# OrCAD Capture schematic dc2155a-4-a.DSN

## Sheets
1 PAGE2: size Custom; title: HIGH VOLTAGE DUAL STEP-DOWN DC/DC CONVERTER; rev: 4; company: TM; note: WITH POWER SYSTEM MANAGEMENT
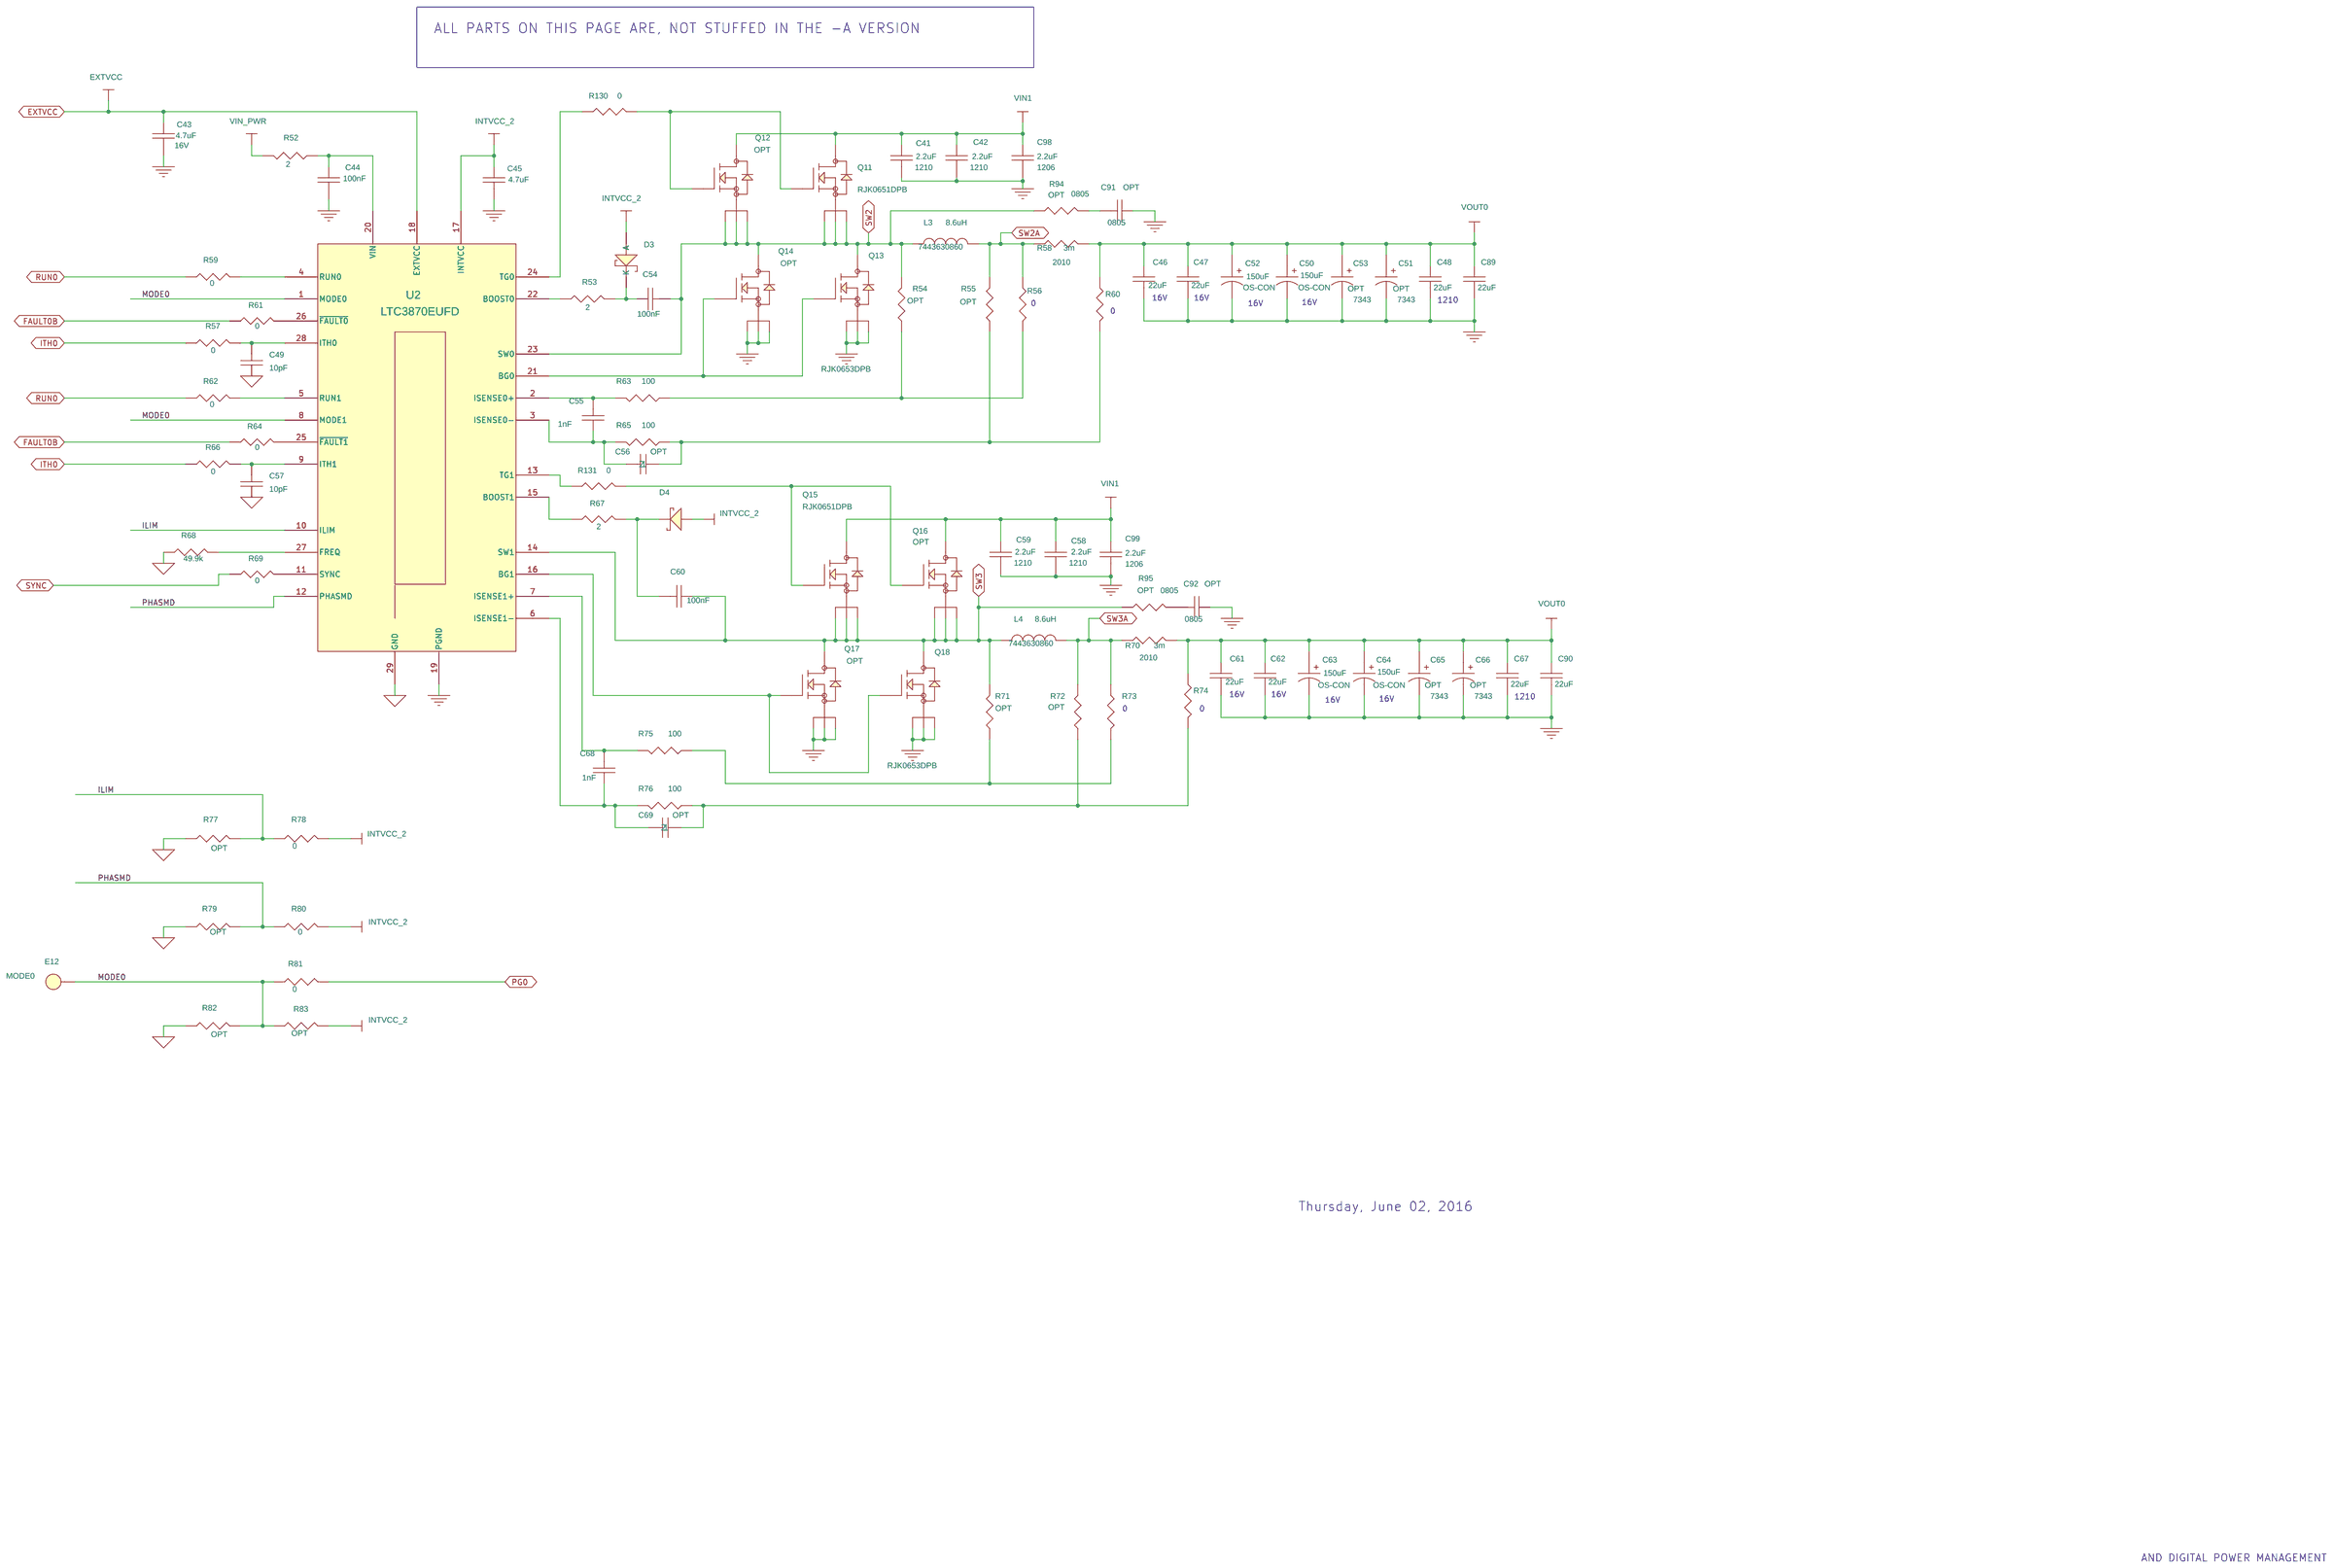
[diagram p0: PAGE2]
2 PAGE1: size Custom; note: DC/DC CONVERTER with POWER SYSTEM MANAGEMENT
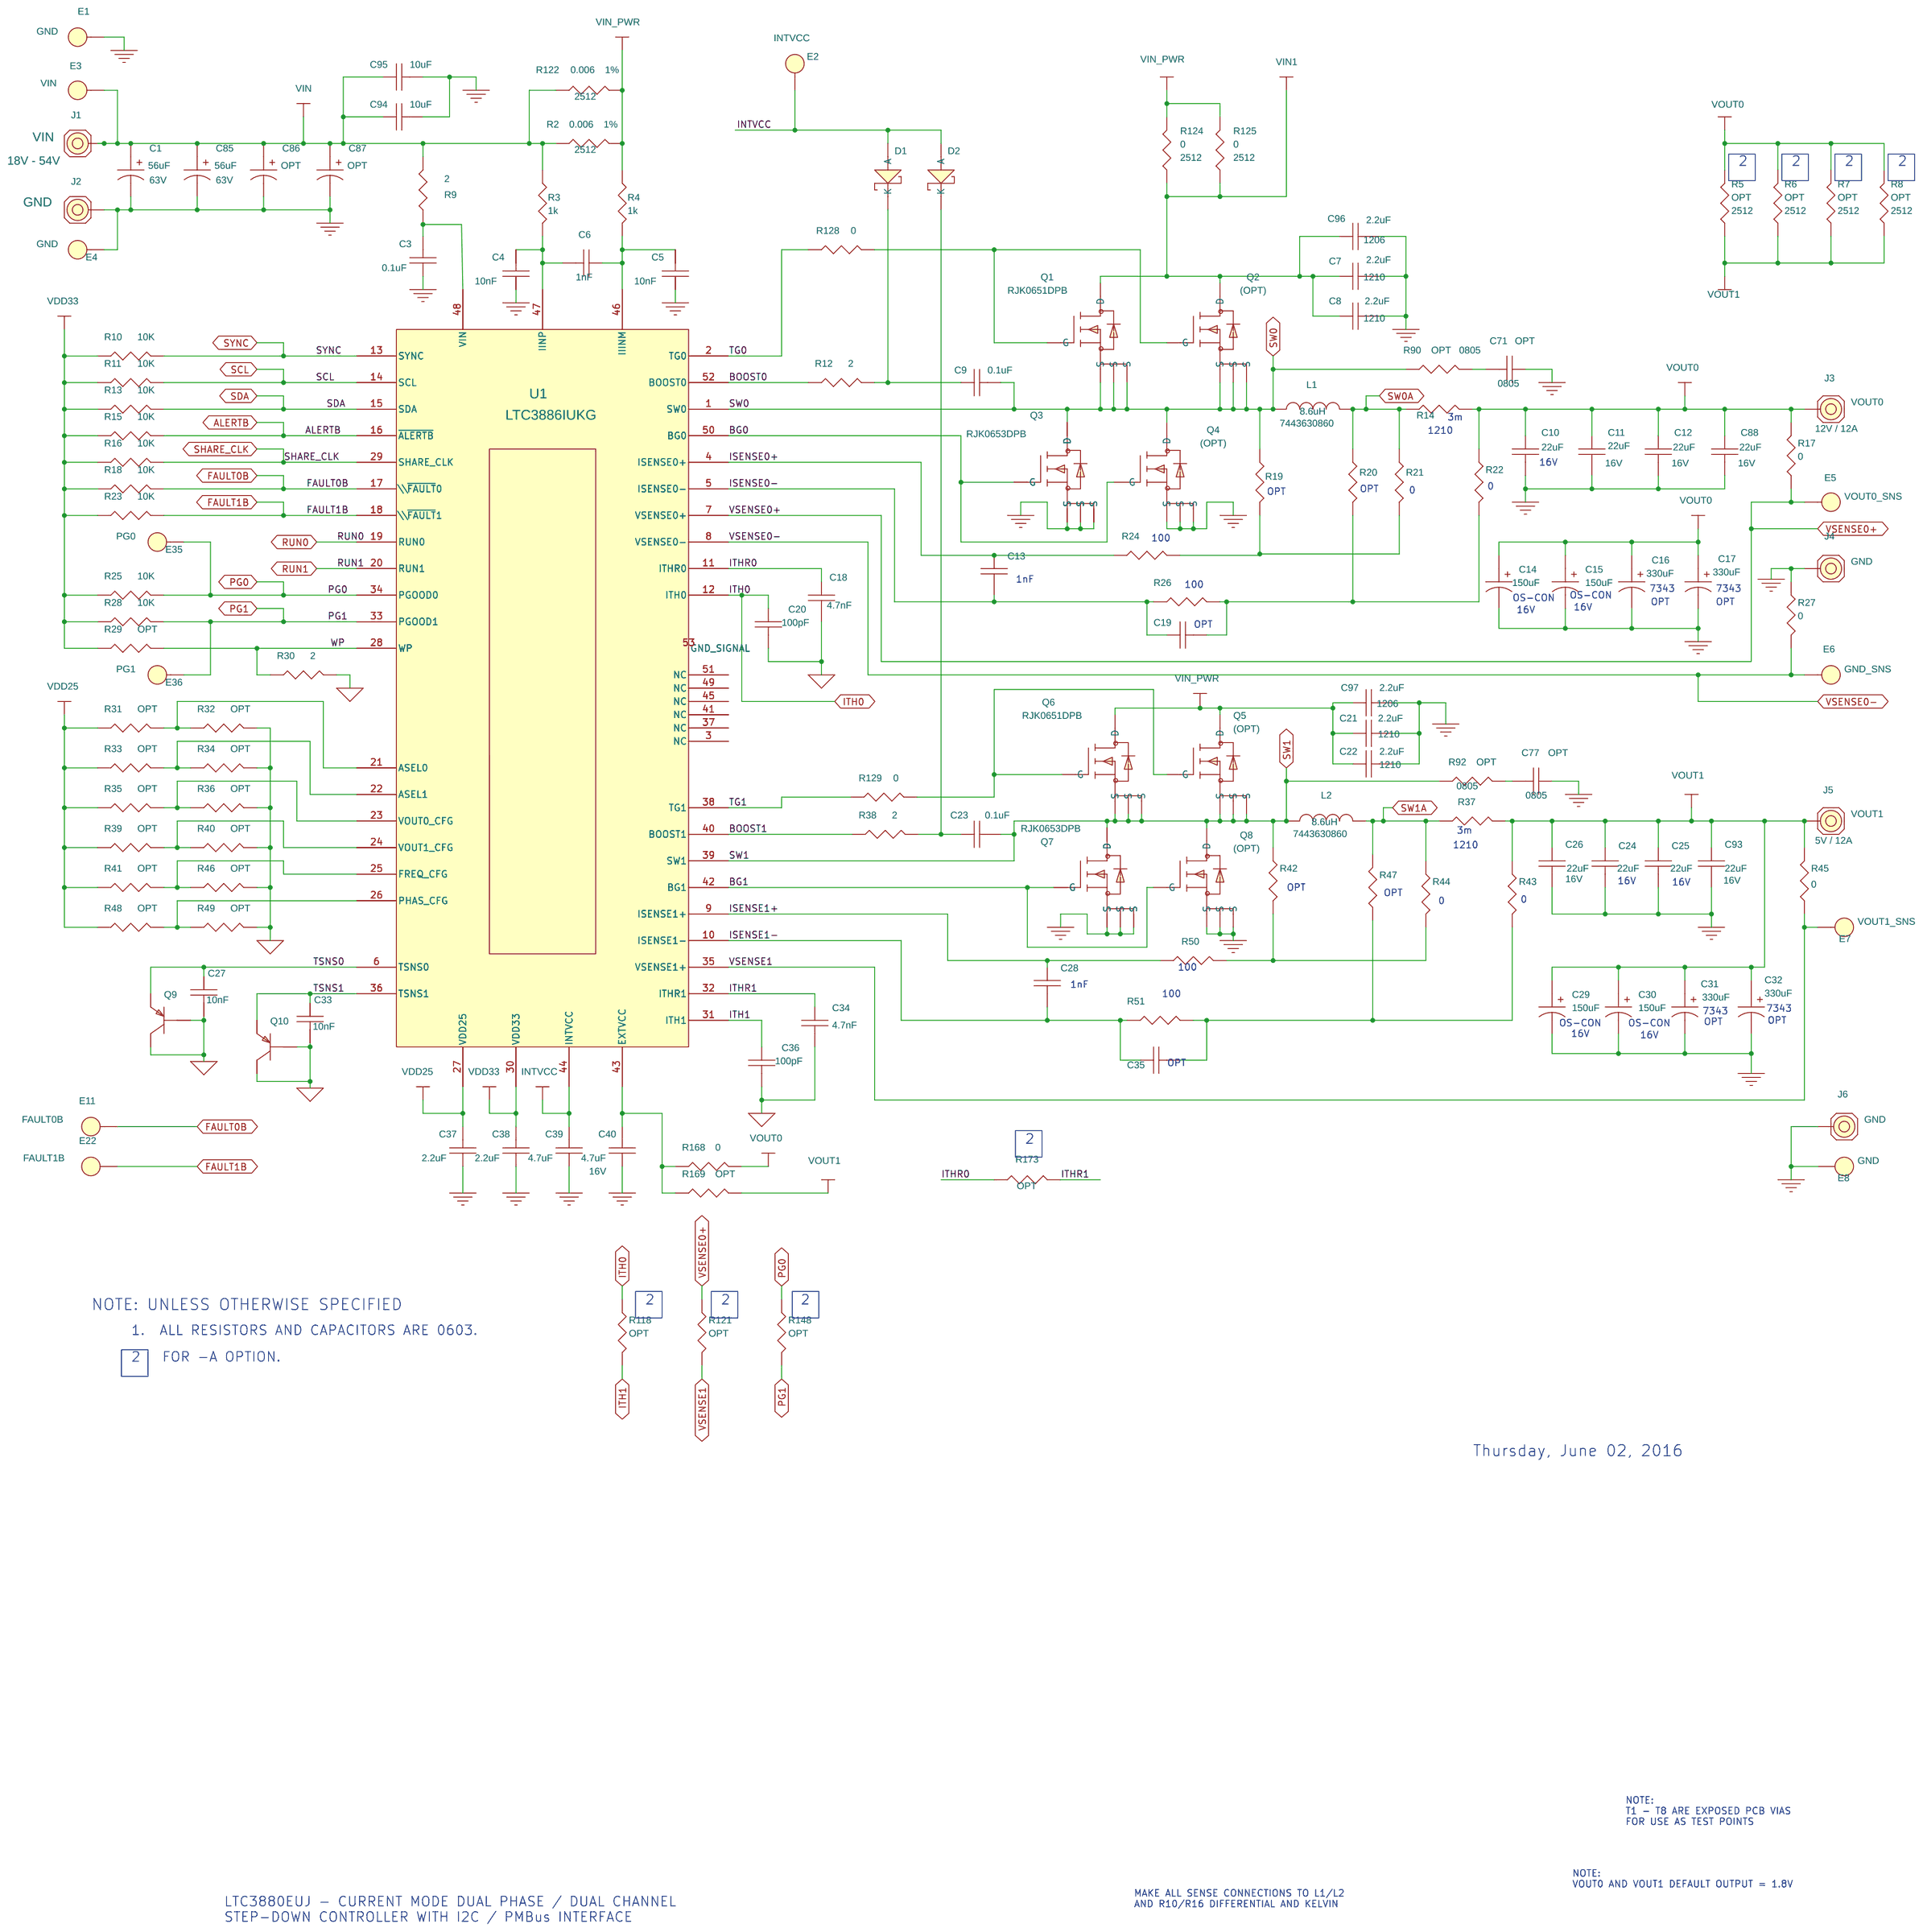
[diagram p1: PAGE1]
3 PAGE3: size Custom
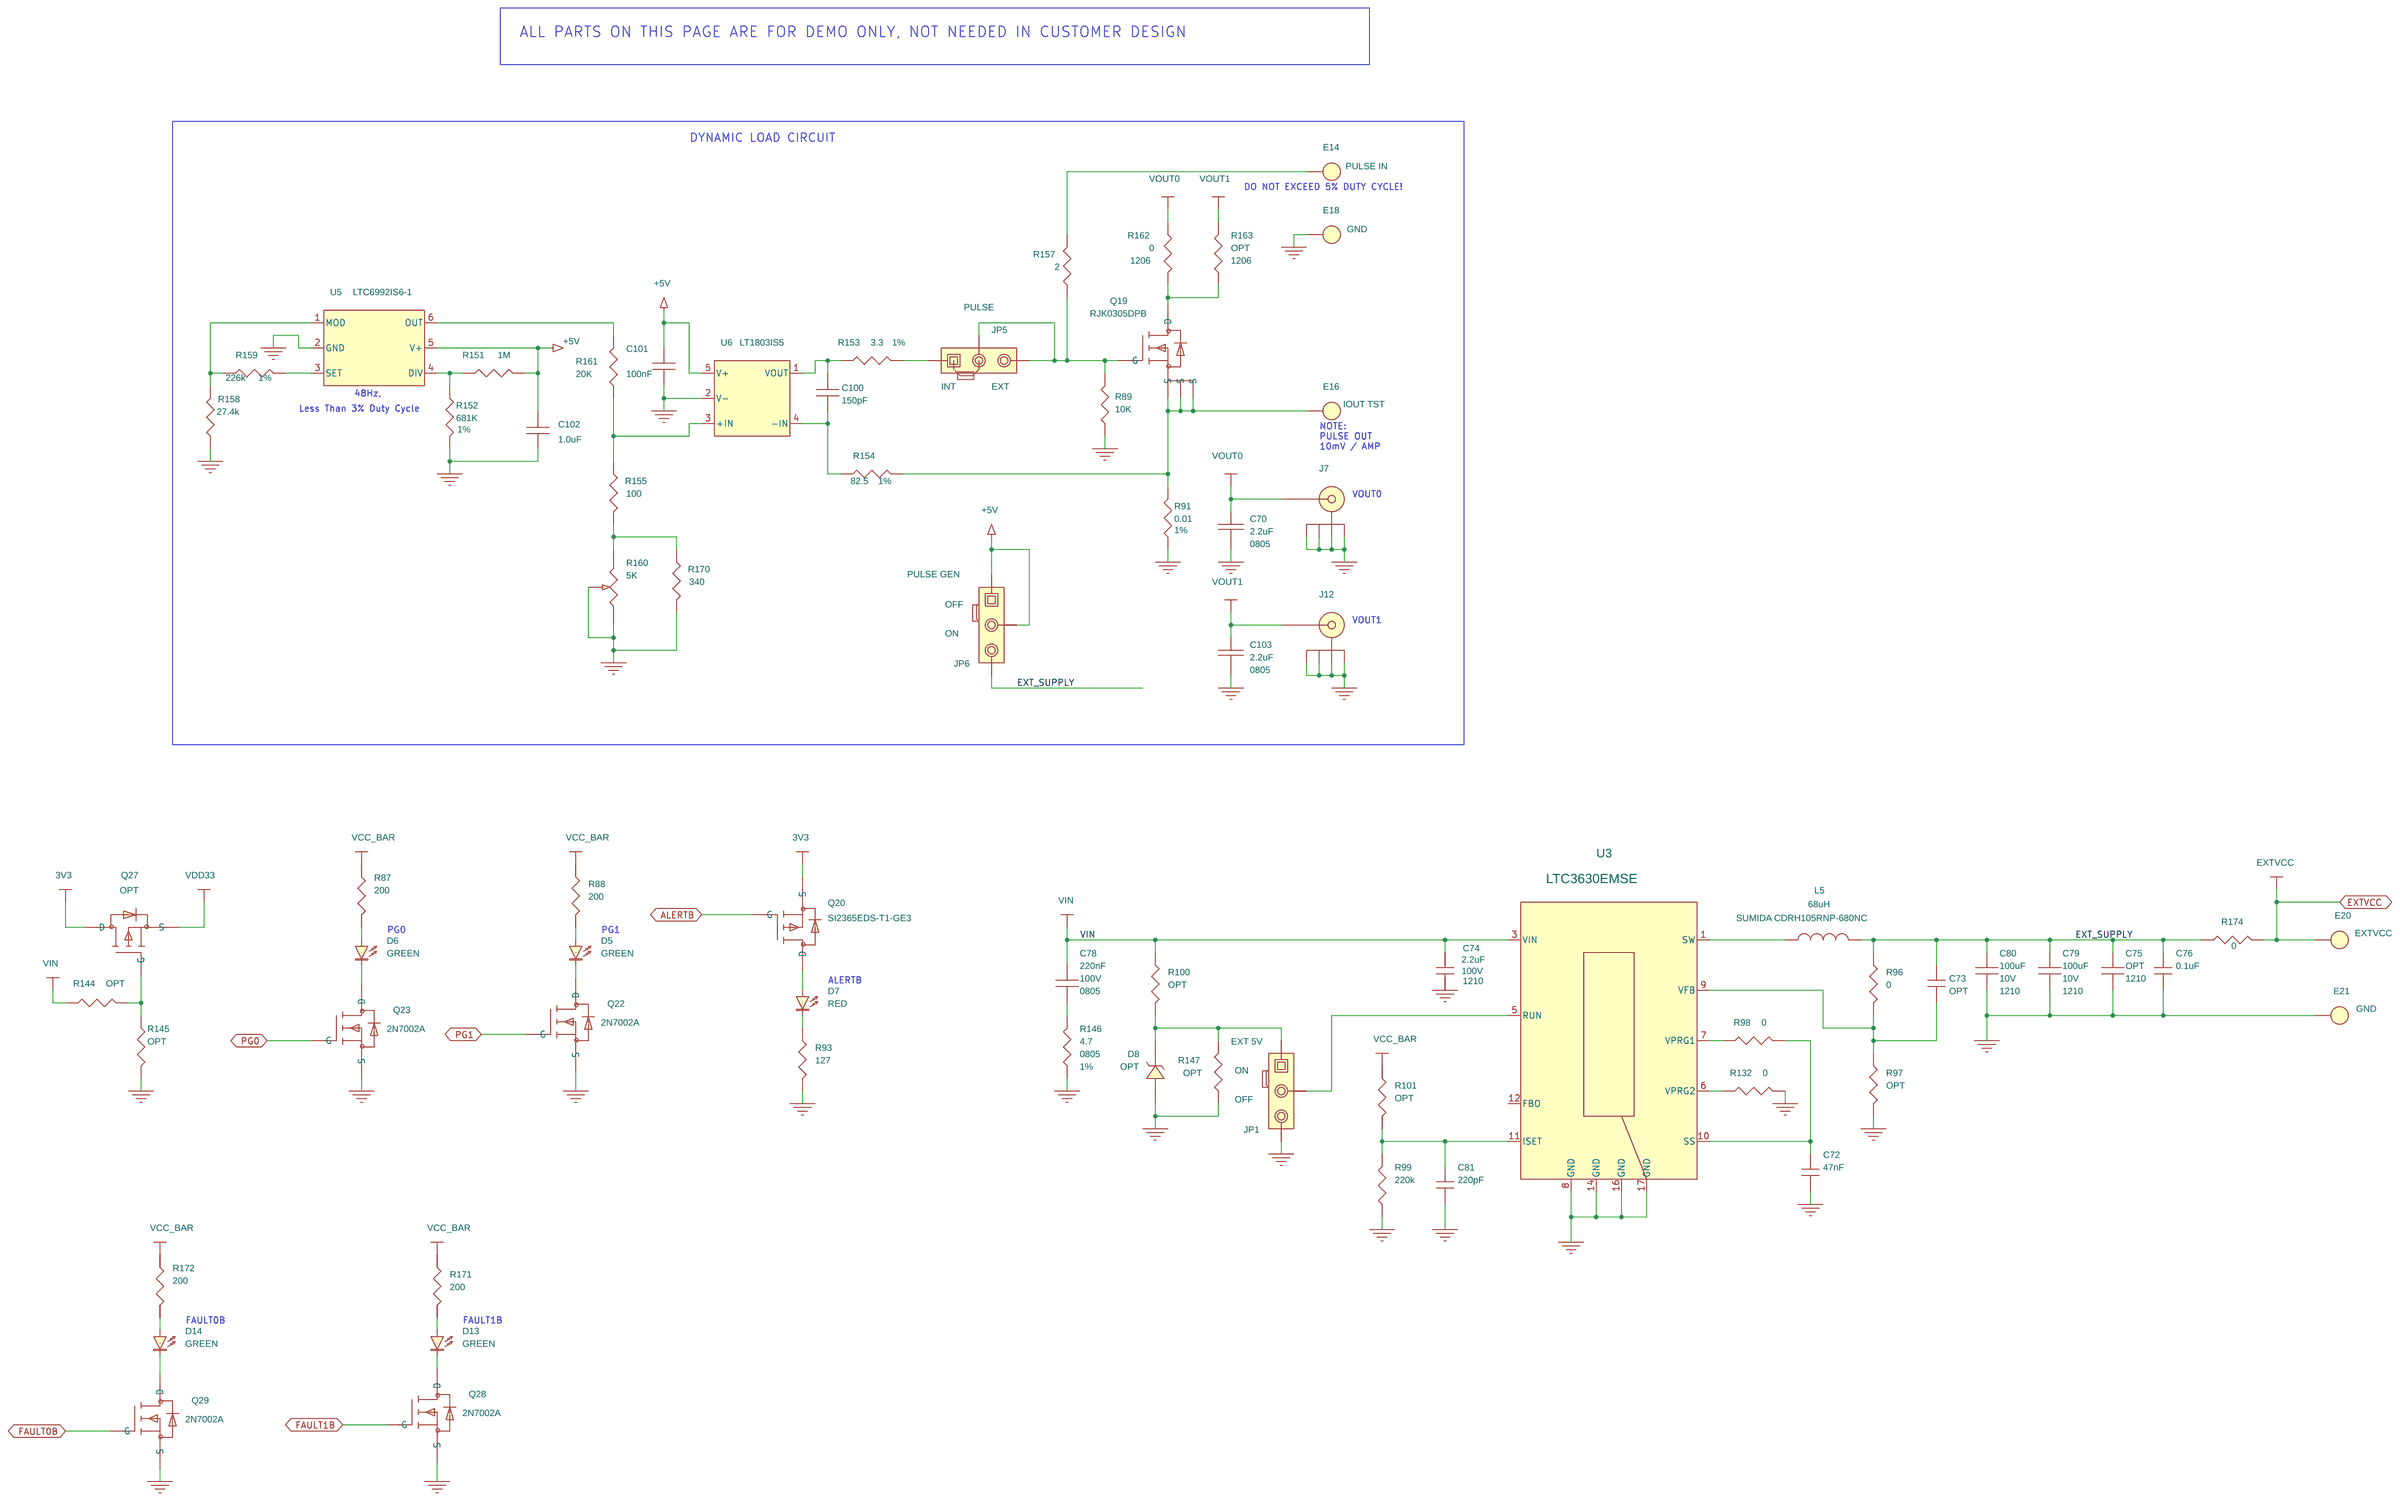
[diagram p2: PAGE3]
4 PAGE4: size B
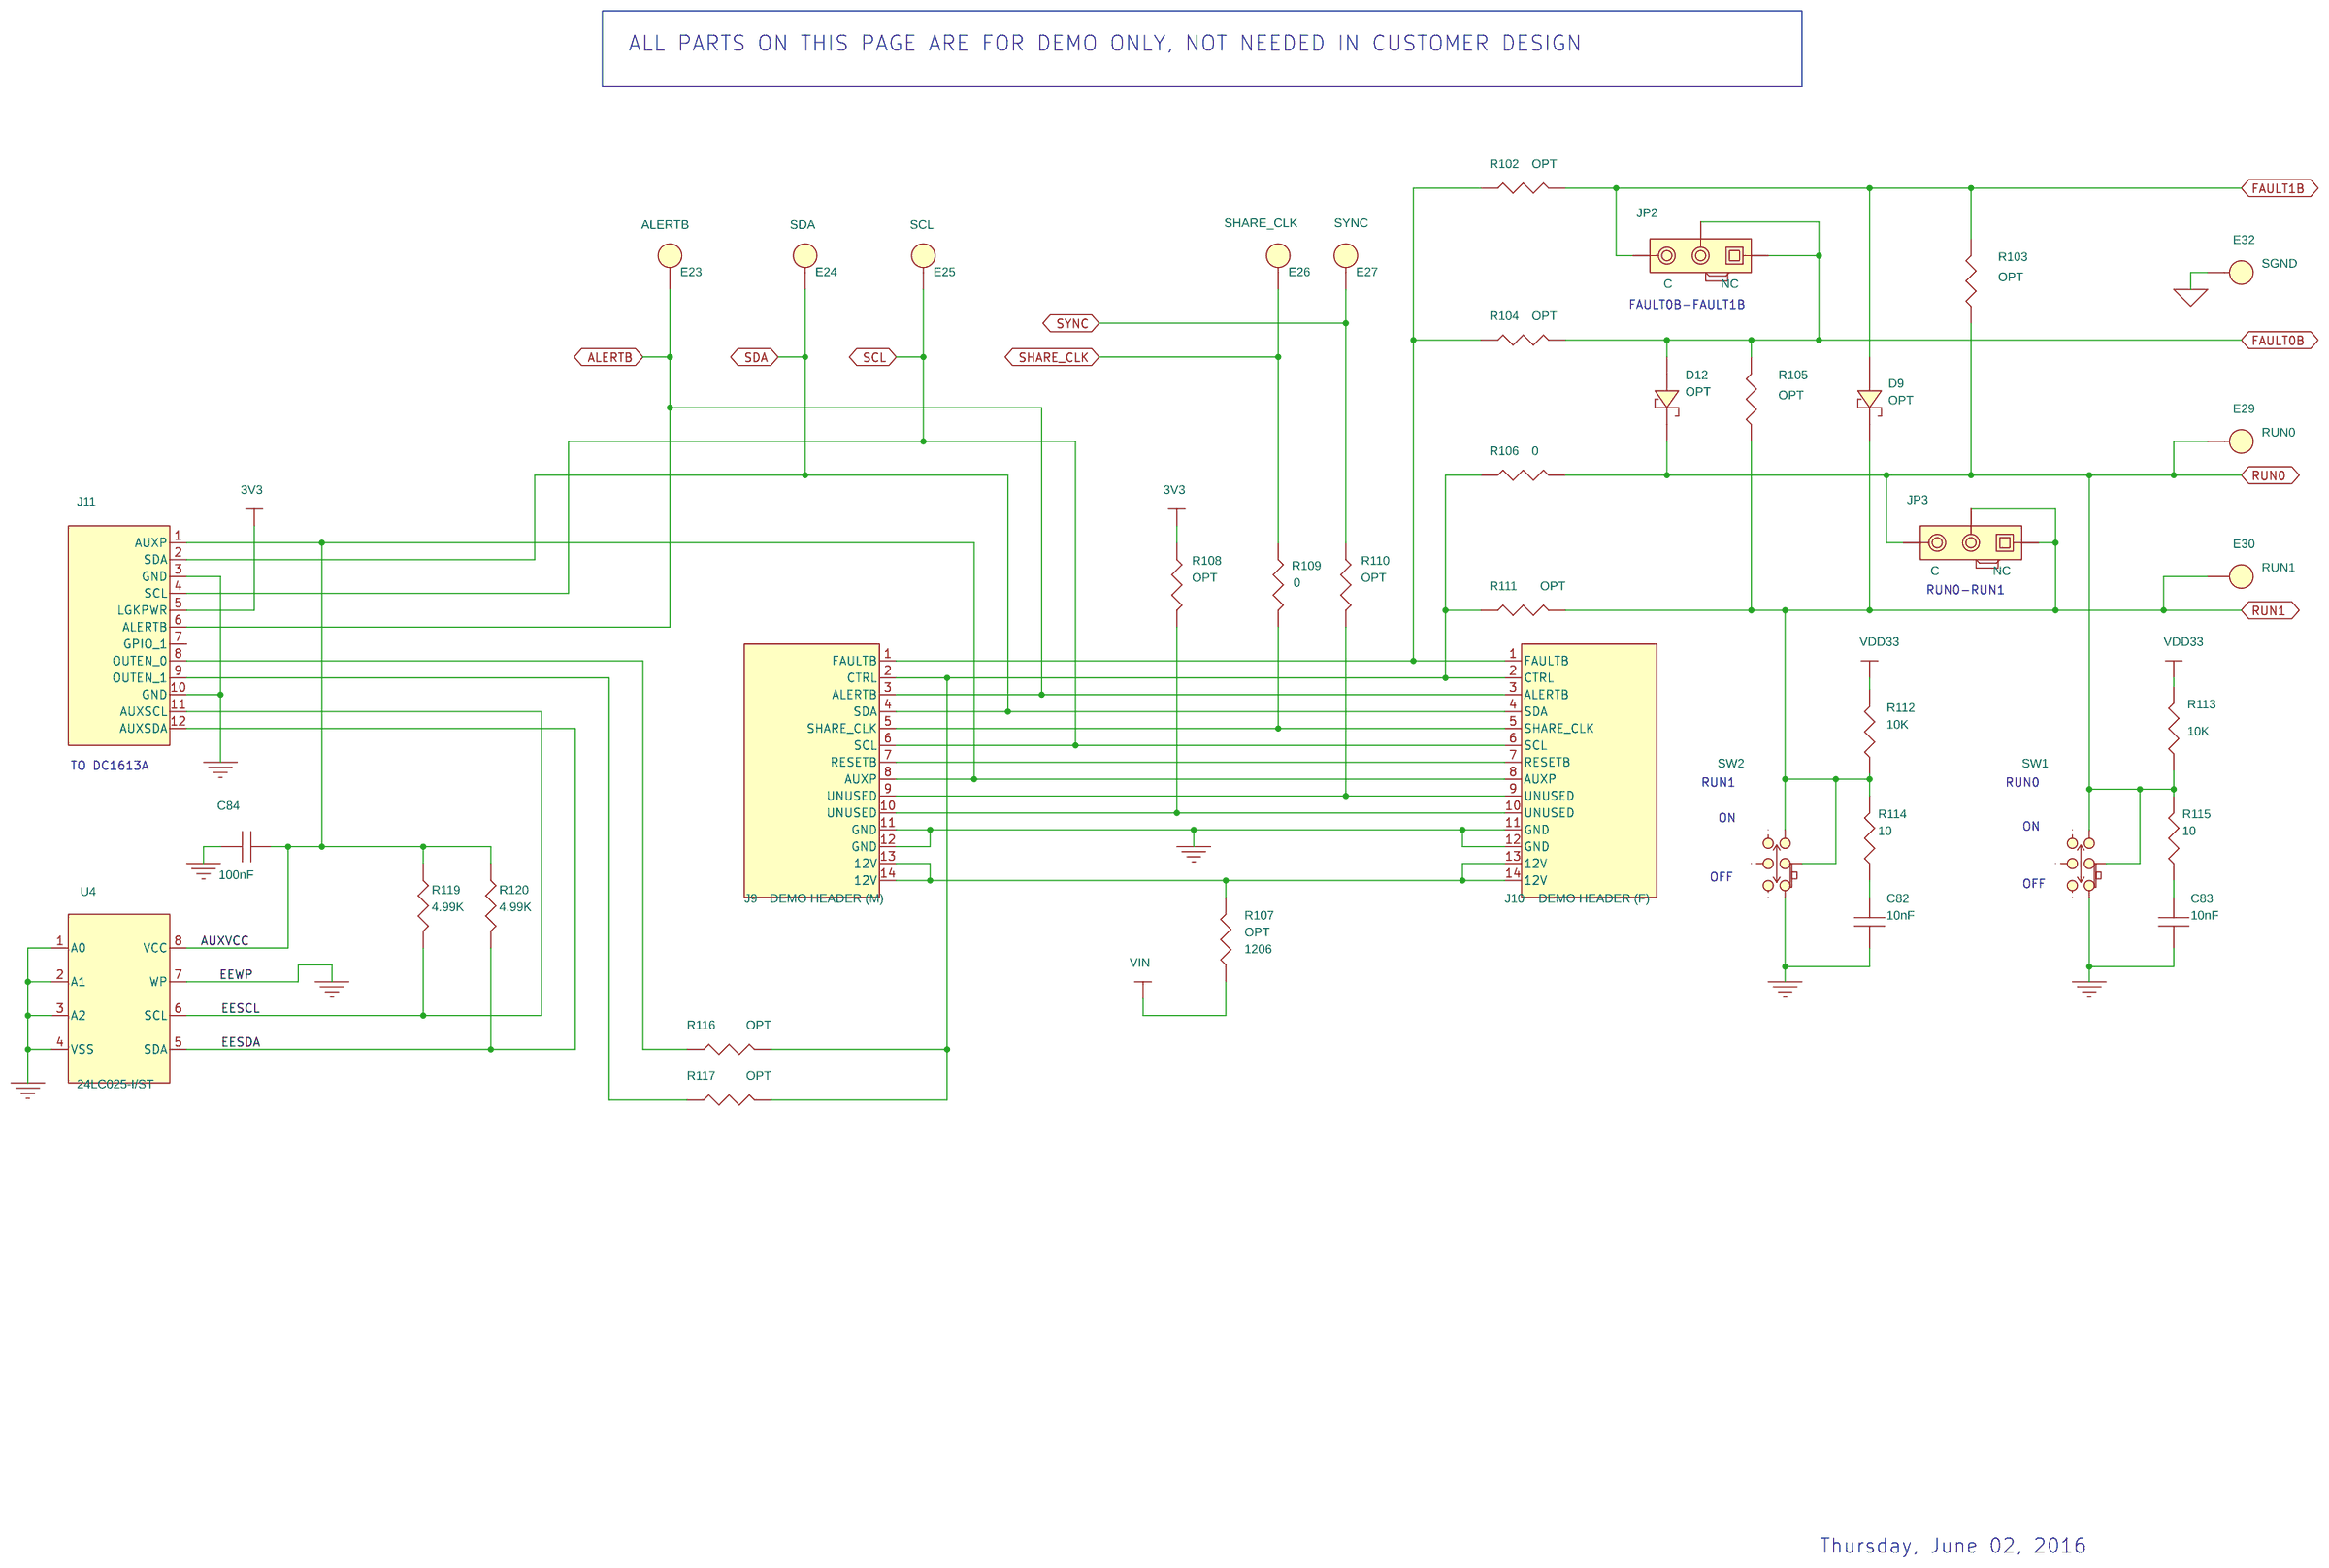
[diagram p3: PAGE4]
5 PAGE5: size A
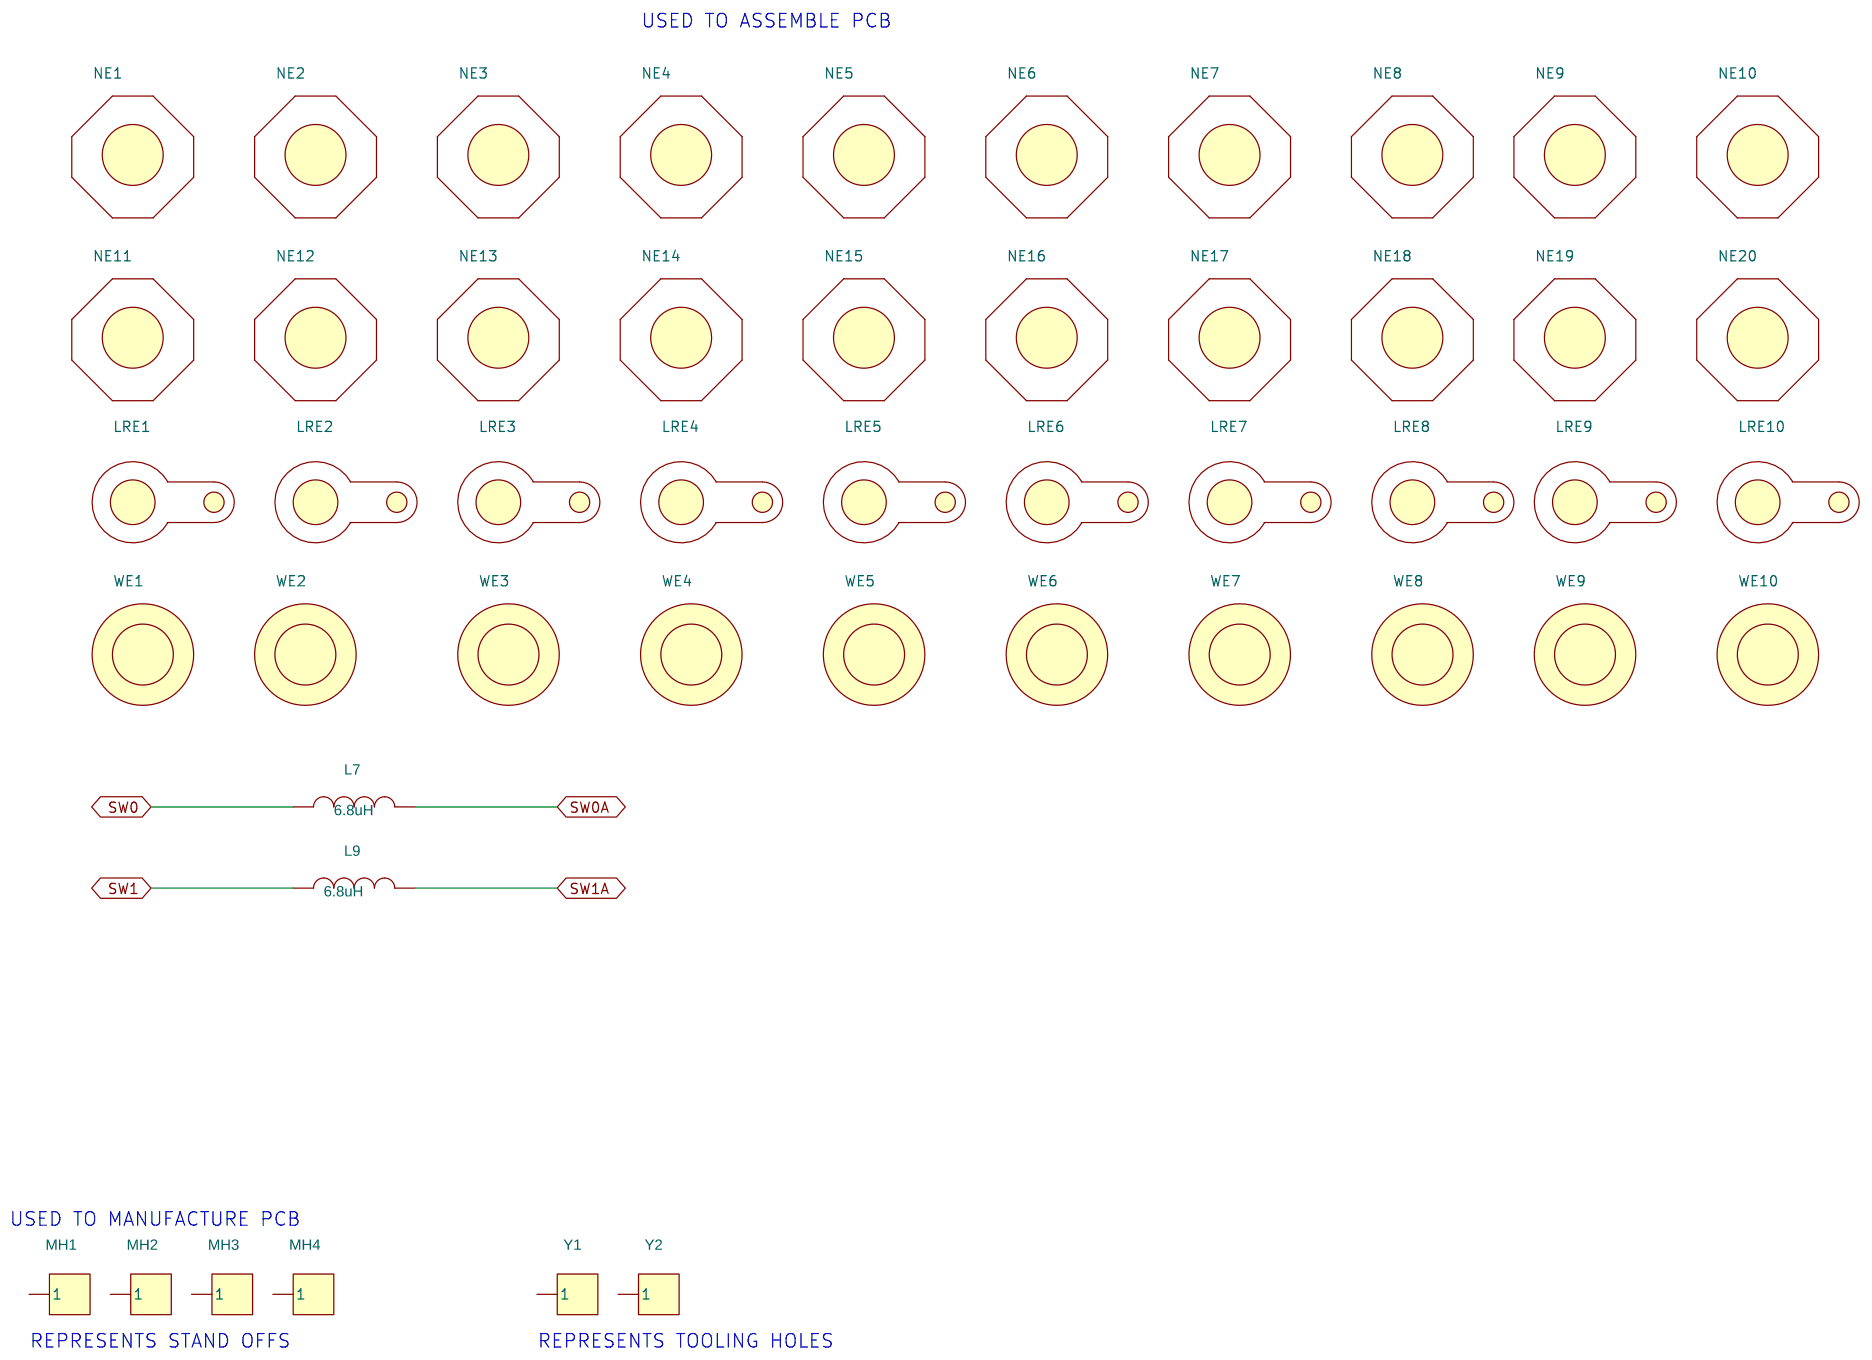
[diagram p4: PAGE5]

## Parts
sheet PAGE1
C1  56uF  [CAP\SUNCON\10X12.5]
C3  0.1uF  [0603]
C4  10nF  [0603]
C5  10nF  [0603]
C6  1nF  [0603]
C7  2.2uF  [1210]
C8  2.2uF  [1812]
C9  0.1uF  [0603]
C10  22uF  [1210]
C11  22uF  [1210]
C12  22uF  [1210]
C13  1nF  [0603]
C14  150uF  [CAP\SANYO\SVP\F8\10.3X10.3]
C15  150uF  [CAP\SANYO\SVP\F8\10.3X10.3]
C16  330uF  [7343]
C17  330uF  [7343]
C18  4.7nF  [0603]
C19  OPT  1.0uF  [0603]
C20  100pF  [0603]
C21  2.2uF  [1812]
C22  2.2uF  [1812]
C23  0.1uF  [0603]
C24  22uF  [1210]
C25  22uF  [1210]
C26  22uF  [1210]
C27  10nF  [0603]
C28  1nF  [0603]
C29  150uF  [CAP\SANYO\SVP\F8\10.3X10.3]
C30  150uF  [CAP\SANYO\SVP\F8\10.3X10.3]
C31  330uF  [7343]
C32  330uF  [7343]
C33  10nF  [0603]
C34  4.7nF  [0603]
C35  OPT 1.0uF  [0603]
C36  100pF  [0603]
C37  2.2uF  [0603]
C38  2.2uF  [0603]
C39  4.7uF  [0603]
C40  4.7uF  [0603]
C71  OPT  [0805]
C77  OPT  [0805]
C85  56uF  [CAP\SUNCON\10X12.5]
C86  OPT  [CAP\SANYO\10X10.2\CE]
C87  OPT  [CAP\SANYO\10X10.2\CE]
C88  22uF  [1210]
C93  22uF  [1210]
C94  10uF  [1812]
C95  10uF  [1812]
C96  2.2uF  [1206]
C97  2.2uF  [1206]
D1  DFLS1100-7  [POWERDI_123]
D2  DFLS1100-7  [POWERDI_123]
E1  PAD150-094  [PAD150-094]
E2  PAD150-094  [PAD150-094]
E3  PAD150-094  [PAD150-094]
E4  PAD150-094  [PAD150-094]
E5  PAD150-094  [PAD150-094]
E6  PAD150-094  [PAD150-094]
E7  PAD150-094  [PAD150-094]
E8  PAD150-094  [PAD150-094]
E11  PAD150-094  [PAD150-094]
E22  PAD150-094  [PAD150-094]
E35  PAD150-094  [PAD150-094]
E36  PAD150-094  [PAD150-094]
J1  Testpin  [con\lug\10]
J2  Testpin  [con\lug\10]
J3  Testpin  [con\lug\10]
J4  Testpin  [con\lug\10]
J5  Testpin  [con\lug\10]
J6  Testpin  [con\lug\10]
L1  8.6uH  [IND\WURTH\7443630860]
L2  8.6uH  [IND\WURTH\7443630860]
Q1  RJK0651DPB  [XSTR\INFINEON\PG-TDSON-8]
Q2  (OPT)  [XSTR\INFINEON\PG-TDSON-8]
Q3  RJK0653DPB  [XSTR\INFINEON\PG-TDSON-8]
Q4  (OPT)  [XSTR\INFINEON\PG-TDSON-8]
Q5  (OPT)  [XSTR\INFINEON\PG-TDSON-8]
Q6  RJK0651DPB  [XSTR\INFINEON\PG-TDSON-8]
Q7  RJK0653DPB  [XSTR\INFINEON\PG-TDSON-8]
Q8  (OPT)  [XSTR\INFINEON\PG-TDSON-8]
Q9  MMBT3906LT1G  [SOT-323]
Q10  MMBT3906LT1G  [SOT-323]
R2  0.006  [2512]
R3  1k  [0603]
R4  1k  [0603]
R5  OPT  [2512]
R6  OPT  [2512]
R7  OPT  [2512]
R8  OPT  [2512]
R9  2  [0603]
R10  10K  [0603]
R11  10K  [0603]
R12  2  [0603]
R13  10K  [0603]
R14  0.003  [2010]
R15  10K  [0603]
R16  10K  [0603]
R17  0  [0603]
R18  10K  [0603]
R19  1.40K  [0603]
R20  0  [0603]
R21  0  [0603]
R22  0  [0603]
R23  10K  [0603]
R24  100  [0603]
R25  10K  [0603]
R26  100  [0603]
R27  0  [0603]
R28  10K  [0603]
R29  OPT  [0603]
R30  2  [0603]
R31  OPT  [0603]
R32  OPT  [0603]
R33  OPT  [0603]
R34  OPT  [0603]
R35  OPT  [0603]
R36  OPT  [0603]
R37  0.003  [2010]
R38  2  [0603]
R39  OPT  [0603]
R40  OPT  [0603]
R41  OPT  [0603]
R42  OPT 1.40K  [0603]
R43  0  [0603]
R44  0  [0603]
R45  0  [0603]
R46  OPT  [0603]
R47  OPT  0  [0603]
R48  OPT  [0603]
R49  OPT  [0603]
R50  100  [0603]
R51  100  [0603]
R90  OPT  [0805]
R92  OPT  [0805]
R118  OPT  [0603]
R121  OPT  [0603]
R122  0.006  [2512]
R124  0  [2512]
R125  0  [2512]
R128  0  [0603]
R129  0  [0603]
R148  OPT  [0603]
R168  0  [0603]
R169  OPT  [0603]
R173  OPT  [0603]
U1  LTC3886IUKG  [LT_UKG52(46)_7mmX8mm]
sheet PAGE2
C41  2.2uF  [1210]
C42  2.2uF  [1210]
C43  4.7uF  [0603]
C44  100nF  [0603]
C45  4.7uF  [0603]
C46  22uF  [1210]
C47  22uF  [1210]
C48  22uF  [1210]
C49  10pF  [0603]
C50  150uF  [CAP\SANYO\SVP\F8\10.3X10.3]
C51  OPT  [7343]
C52  150uF  [CAP\SANYO\SVP\F8\10.3X10.3]
C53  OPT  [7343]
C54  100nF  [0603]
C55  1nF  [0603]
C56  OPT  [0603]
C57  10pF  [0603]
C58  2.2uF  [1210]
C59  2.2uF  [1210]
C60  100nF  [0603]
C61  22uF  [1210]
C62  22uF  [1210]
C63  150uF  [CAP\SANYO\SVP\F8\10.3X10.3]
C64  150uF  [CAP\SANYO\SVP\F8\10.3X10.3]
C65  OPT  [7343]
C66  OPT  [7343]
C67  22uF  [1210]
C68  1nF  [0603]
C69  OPT  [0603]
C89  22uF  [1210]
C90  22uF  [1210]
C91  OPT  [0805]
C92  OPT  [0805]
C98  2.2uF  [1206]
C99  2.2uF  [1206]
D3  DFLS1100-7  [POWERDI_123]
D4  DFLS1100-7  [POWERDI_123]
E12  PAD150-094  [PAD150-094]
L3  8.6uH  [IND\WURTH\7443630860]
L4  8.6uH  [IND\WURTH\7443630860]
Q11  RJK0651DPB  [XSTR\INFINEON\PG-TDSON-8]
Q12  OPT  [XSTR\INFINEON\PG-TDSON-8]
Q13  RJK0653DPB  [XSTR\INFINEON\PG-TDSON-8]
Q14  OPT  [XSTR\INFINEON\PG-TDSON-8]
Q15  RJK0651DPB  [XSTR\INFINEON\PG-TDSON-8]
Q16  OPT  [XSTR\INFINEON\PG-TDSON-8]
Q17  OPT  [XSTR\INFINEON\PG-TDSON-8]
Q18  RJK0653DPB  [XSTR\INFINEON\PG-TDSON-8]
R52  2  [0603]
R53  2  [0603]
R54  OPT  [0603]
R55  OPT  [0603]
R56  0  [0603]
R57  0  [0603]
R58  3m  [2010]
R59  0  [0603]
R60  0  [0603]
R61  0  [0603]
R62  0  [0603]
R63  100  [0603]
R64  0  [0603]
R65  100  [0603]
R66  0  [0603]
R67  2  [0603]
R68  49.9k  [0603]
R69  0  [0603]
R70  3m  [2010]
R71  OPT  [0603]
R72  OPT  [0603]
R73  0  [0603]
R74  0  [0603]
R75  100  [0603]
R76  100  [0603]
R77  OPT  [0603]
R78  0  [0603]
R79  OPT  [0603]
R80  0  [0603]
R81  0  [0603]
R82  OPT  [0603]
R83  OPT  [0603]
R94  OPT  [0805]
R95  OPT  [0805]
R130  0  [0603]
R131  0  [0603]
U2  LTC3870EUFD  [LT_UFD28_4X5]
sheet PAGE3
C70  2.2uF  [0805]
C72  47nF  [0603]
C73  OPT  [0603]
C74  2.2uF  [1210]
C75  OPT  [1210]
C76  0.1uF  [0603]
C78  220nF  [0805]
C79  100uF  [1210]
C80  100uF  [1210]
C81  220pF  [0603]
C100  150pF  [0603]
C101  100nF  [0603]
C102  1.0uF  [0603]
C103  2.2uF  [0805]
D5  GREEN  [LED_0603]
D6  GREEN  [LED_0603]
D7  RED  [LED_0603]
D8  OPT  [SOD123]
D13  GREEN  [LED_0603]
D14  GREEN  [LED_0603]
E14  PAD150-094  [PAD150-094]
E16  PAD150-094  [PAD150-094]
E18  PAD150-094  [PAD150-094]
E20  PAD150-094  [PAD150-094]
E21  PAD150-094  [PAD150-094]
J7  XXX  [BNC5]
J12  XXX  [BNC5]
JP1  3 Pins 2mm Ctrs.  [SIP\3P\2MM]
JP5  3 Pins 2mm Ctrs.  [SIP\3P\2MM]
JP6  3 Pins 2mm Ctrs.  [SIP\3P\2MM]
L5  68uH  [IND\SUMIDA\CDRH105R\12X12]
Q19  RJK0305DPB  [LFPAK]
Q20  SI2365EDS-T1-GE3  [SOT23]
Q22  2N7002A  [SOT23]
Q23  2N7002A  [SOT23]
Q27  OPT  [SOT23]
Q28  2N7002A  [SOT23]
Q29  2N7002A  [SOT23]
R87  200  [0603]
R88  200  [0603]
R89  10K  [0603]
R91  0.01  [2010]
R93  127  [0603]
R96  0  [0603]
R97  OPT  [0603]
R98  0  [0603]
R99  220k  [0603]
R100  OPT  [0603]
R101  OPT  [0603]
R132  0  [0603]
R144  OPT  [0603]
R145  OPT  [0603]
R146  4.7  [0805]
R147  OPT  [0603]
R151  1M  [0603]
R152  681K  [0603]
R153  3.3  [0603]
R154  82.5  [0603]
R155  100  [0603]
R157  2  [0603]
R158  27.4k  [0603]
R159  226k  [0603]
R160  5K  [BOURNS_3386P]
R161  20K  [0603]
R162  0  [1206]
R163  OPT  [1206]
R170  340  [0603]
R171  200  [0603]
R172  200  [0603]
R174  0  [0603]
U3  LTC3630EMSE  [LT_MSE16_12]
U5  LTC6992IS6-1  [LT_S6]
U6  LT1803IS5  [LT_S5]
XJP1  2mm Ctrs.
XJP5  2mm Ctrs.
XJP6  2mm Ctrs.
sheet PAGE4
C82  10nF  [0603]
C83  10nF  [0603]
C84  100nF  [0603]
D9  OPT  [SOD323]
D12  OPT  [SOD323]
E23  ALERTB  [PAD150-094]
E24  SDA  [PAD150-094]
E25  SCL  [PAD150-094]
E26  SHARE_CLK  [PAD150-094]
E27  SYNC  [PAD150-094]
E29  RUN0  [PAD150-094]
E30  RUN1  [PAD150-094]
E32  SGND  [PAD150-094]
J9  DEMO HEADER (M)  [NPPN072FJFN]
J10  DEMO HEADER (F)  [NPPN072FJFN-RC]
J11  HD2X6-079  [HD2X6-079-MOLEX]
JP2  3 Pins 2mm Ctrs.  [SIP\3P\2MM]
JP3  3 Pins 2mm Ctrs.  [SIP\3P\2MM]
R102  OPT  [0603]
R103  OPT  [0603]
R104  OPT  [0603]
R105  OPT  [0603]
R106  0  [0603]
R107  OPT  [1206]
R108  OPT  [0603]
R109  0  [0603]
R110  OPT  [0603]
R111  OPT  [0603]
R112  10K  [0603]
R113  10K  [0603]
R114  10  [0603]
R115  10  [0603]
R116  OPT  [0603]
R117  OPT  [0603]
R119  4.99K  [0603]
R120  4.99K  [0603]
SW1  JP3X1/079\NO\12  [JS202011]
SW2  JP3X1/079\NO\12  [JS202011]
U4  24LC025-I/ST  [TSSOP-8_4.4MM]
XJP2  2mm Ctrs.
XJP3  2mm Ctrs.
sheet PAGE5
L7  6.8uH  [IND\CLCRFT\SER2900]
L9  6.8uH  [IND\CLCRFT\SER2900]
LRE1  Lug_Ring
LRE2  Lug_Ring
LRE3  Lug_Ring
LRE4  Lug_Ring
LRE5  Lug_Ring
LRE6  Lug_Ring
LRE7  Lug_Ring
LRE8  Lug_Ring
LRE9  Lug_Ring
LRE10  Lug_Ring
MH1  CON1  [KEYSTONE_8831]
MH2  CON1  [KEYSTONE_8831]
MH3  CON1  [KEYSTONE_8831]
MH4  CON1  [KEYSTONE_8831]
NE1  NUT
NE2  NUT
NE3  NUT
NE4  NUT
NE5  NUT
NE6  NUT
NE7  NUT
NE8  NUT
NE9  NUT
NE10  NUT
NE11  NUT
NE12  NUT
NE13  NUT
NE14  NUT
NE15  NUT
NE16  NUT
NE17  NUT
NE18  NUT
NE19  NUT
NE20  NUT
WE1  Washer
WE2  Washer
WE3  Washer
WE4  Washer
WE5  Washer
WE6  Washer
WE7  Washer
WE8  Washer
WE9  Washer
WE10  Washer
Y1  CON1  [TOOL\ALGNHL\70]
Y2  CON1  [TOOL\ALGNHL\70]

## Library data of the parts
C1 C85 = CAP_POL: CAP, 56uF 20% 63V ELEC; Part Number: SUNCON 63HVP56M; VOLTAGE: 63V
C3 C9 C23 = CAP0603_1: CAP, 0603 0.1uF 10% 100V X7R; Component: cap; Manufacturer: TDK; Manufacturer P/N: C1608X7R1H104K; Part Number: MURATA GRM188R72A104KA35D; Tolerance: 10%; Type: cer 0603 X7R; Vendor: Digikey; Vendor P/N: 445-1314-1-ND
C4 C5 = CAP0603_1: CAP, 0603 10nF 10% 100V X7R; Component: cap; Manufacturer: TDK; Manufacturer P/N: C1608X7R1H104K; Part Number: MURATA GRM188R72A103KA01D; Tolerance: 10%; Type: cer 0603 X7R; Vendor: Digikey; Vendor P/N: 445-1314-1-ND
C6 = CAP0603_1: CAP, 0603 1nF 10% 100V X7R; Component: cap; Manufacturer: TDK; Manufacturer P/N: C1608X7R1H104K; Part Number: AVX 06031C102KAT2A; Tolerance: 10%; Type: cer 0603 X7R; Vendor: Digikey; Vendor P/N: 445-1314-1-ND; Volts/Amps/Watts: 50V
C7 C41 C42 C58 C59 = CAP1210_1: CAP, 1210 2.2uF 10% 100V X7R; Component: cap; Part Number: MURATA GRM32ER72A225KA35L; Tolerance: 10%; Type: cer 1210; Vendor: Digikey; Vendor P/N: 587-1439-1-ND; Volts/Amps/Watts: 100V
C8 C21 C22 = CAP1210_1: CAP, 1210 2.2uF 10% 100V X7R; 1st Part Field: 1210; Component: cap; Part Number: MURATA GRM32ER72A225KA35L; Tolerance: 10%; Type: cer 1210; Vendor: Digikey; Vendor P/N: 587-1439-1-ND; Volts/Amps/Watts: 100V
C10-C12 C24-C26 C88 C93 = CAP0603_1: CAP, 1210 22uF 20% 16V X7R; Component: cap; Manufacturer: TDK; Manufacturer P/N: C3225X5R0J107M; Part Number: AVX 1210YC226MAT2A; Part Type: CAP1210; Tolerance: 20%; Type: cer 1210 X5R; Vendor: Digikey; Vendor P/N: 445-1437-1-ND; Volts/Amps/Watts: 16V
C13 C28 = CAP0603_1: CAP, 0603 1nF 10% 16V X7R; Component: cap; Manufacturer: AVX; Manufacturer P/N: 06035C102KAT2A; Part Number: AVX 0603YC102KAT2A; Tolerance: 10%; Type: cer 0603 X7R; Vendor: Digikey; Vendor P/N: 478-1215-1-ND; Volts/Amps/Watts: 50V
C14 C29 C30 = CAPR12X5_0: CAP, 150uF 16V ELEC. OS-CON; Component: cap; Manufacturer: SANYO; Manufacturer P/N: 6TPF330M9L; Part Number: PANASONIC 16SVP150M; Tolerance: 20%; Type: TANT; Volts/Amps/Watts: 6.3V
C15 = CAPR12X5_0: CAP, 150uF 16V ELEC. OS-CON; Component: cap; Manufacturer: SANYO; Manufacturer P/N: 6TPF330M9L; Part Number: PANASONIC 16SVP150M; Part Type: CAP7343-43; Tolerance: 20%; Type: TANT; Volts/Amps/Watts: 6.3V
C16 C17 C31 C32 C51 C53 C65 C66 = CAPR12X5_0: CAP, 7343 OPTION; Component: cap; Manufacturer: SANYO; Manufacturer P/N: 6TPF330M9L; Part Number: OPTION; Tolerance: 20%; Type: TANT; Volts/Amps/Watts: 6.3V
C18 C34 = CAP0603_1: CAP, 0603 4.7nF 10% 50V X7R; Component: cap; Manufacturer: TDK; Manufacturer P/N: C1608C0G1H102J; Part Number: AVX 06035C472KAT2A; Tolerance: 5%; Type: cer 0603; Vendor: Digikey; Vendor P/N: 445-1293-1-ND; Volts/Amps/Watts: 50V
C19 C35 = CAP0603_1: CAP, 0603 OPTION; Manufacturer: Taiyo Yuden; Manufacturer P/N: EMK107B7105KA-T; Part Number: OPTION; Type: cer 0603 X7R; Vendor: Digikey; Vendor P/N: 587-1241-1-ND; Volts/Amps/Watts: 16V
C20 C36 = CAP0603_1: CAP, 0603 100pF 5% 50V C0G; Component: cap; Manufacturer: TDK; Manufacturer P/N: C1608C0G1H101J; Part Number: AVX 06035A101JAT2A; Tolerance: 5%; Type: cer 0603; Vendor: Digikey; Vendor P/N: 445-1281-1-ND
C27 C33 = CAP0603_1: CAP, 0603 10nF 10% 100V X7R; Component: cap; Manufacturer: TDK; Manufacturer P/N: C1608X7R1H103K; Part Number: MURATA GRM188R72A103KA01D; Tolerance: 10%; Type: cer 0603; Vendor: Digikey; Vendor P/N: 445-1311-1-ND; Volts/Amps/Watts: 50V
C37 C38 = CAP0603_1: CAP, 0603 2.2uF 10% 16V X5R; Component: cap; Manufacturer: TDK; Manufacturer P/N: C1608X7R1H104K; Part Number: AVX 0603YD225KAT2A; Tolerance: 10%; Type: cer 0603 X7R; Vendor: Digikey; Vendor P/N: 445-1314-1-ND; Volts/Amps/Watts: 50V
C39 = CAP0603_1: CAP, 0603 4.7uF 10% 10V X5R; Component: cap; Manufacturer: TDK; Manufacturer P/N: C1608X7R1H104K; Part Number: AVX 0603ZD475KAT2A; Tolerance: 10%; Type: cer 0603 X7R; Vendor: Digikey; Vendor P/N: 445-1314-1-ND; Volts/Amps/Watts: 50V
C40 = CAP0603_1: CAP, 0603 4.7uF 10% 16V X5R; Component: cap; Manufacturer: TDK; Manufacturer P/N: C1608X7R1H104K; Part Number: MURATA GRM188R61C475KAAJD; Tolerance: 10%; Type: cer 0603 X7R; Vendor: Digikey; Vendor P/N: 445-1314-1-ND; Volts/Amps/Watts: 16V
C71 C77 C91 C92 = CAP0603_1: CAP, 0805 OPTION; Component: cap; Manufacturer: TDK; Manufacturer P/N: C1608X7R1H104K; Part Number: OPTION; Tolerance: 10%; Type: cer 0603 X7R; Vendor: Digikey; Vendor P/N: 445-1314-1-ND; Volts/Amps/Watts: 50V
C86 C87 = CAP_POL: CAP, ELEC OPTION; Part Number: OPTION; VOLTAGE: 63V
C94 C95 = CAP1210_1: CAP, 1812 10uF 20% 100V X7S; Component: cap; Manufacturer: Taiyo Yuden; Manufacturer P/N: GMK325BJ106KN-T; Part Number: TDK CKG45NX7S2A106M500JH; Tolerance: 10%; Type: cer 1210; Vendor: Digikey; Vendor P/N: 587-1439-1-ND; Volts/Amps/Watts: 100V
C96-C99 = CAP0603_1: CAP, 1206 2.2uF 10% 100V X7R; Component: cap; Manufacturer: TDK; Manufacturer P/N: C1608X7R1H104K; Part Number: MURATA GRM31CR72A225KA73L; Tolerance: 10%; Type: cer 0603 X7R; Vendor: Digikey; Vendor P/N: 445-1314-1-ND; Volts/Amps/Watts: 100V
D1 D3 = cmdsh-3_1: DIODE, SCHOTTKY 100V, 1A; Component: diode; Manufacturer: Central; Manufacturer P/N: CMDSH-3TR; Part Number: DIODES/ZETEX, DFLS1100-7; Type: Schottky; Vendor: Mouser; Vendor P/N: 610-CMDSH-3; Volts/Amps/Watts: 30V 100mA
D2 = cmdsh-3_2: DIODE, SCHOTTKY 100V, 1A; Component: diode; Manufacturer: Central; Manufacturer P/N: CMDSH-3TR; Part Number: DIODES/ZETEX, DFLS1100-7; Type: Schottky; Vendor: Mouser; Vendor P/N: 610-CMDSH-3; Volts/Amps/Watts: 30V 100mA
E1 E4 E8 E18 = E: TURRET; 10th Part Field: 3.3V / 3A; 9th Part Field: GND; Part Number: MILL-MAX 2501-2-00-80-00-00-07-0
E2 = E: TURRET; 10th Part Field: 3.3V / 3A; 9th Part Field: INTVCC; Part Number: MILL-MAX 2501-2-00-80-00-00-07-0
E3 = E: TURRET; 10th Part Field: 3.3V / 3A; 9th Part Field: VIN; Part Number: MILL-MAX 2501-2-00-80-00-00-07-0
E5 = E: TURRET; 10th Part Field: 3.3V / 3A; 9th Part Field: VOUT0_SNS; Part Number: MILL-MAX 2501-2-00-80-00-00-07-0
E6 = E: TURRET; 10th Part Field: 3.3V / 3A; 9th Part Field: GND_SNS; Part Number: MILL-MAX 2501-2-00-80-00-00-07-0
E7 = E: TURRET; 10th Part Field: 3.3V / 3A; 9th Part Field: VOUT1_SNS; Part Number: MILL-MAX 2501-2-00-80-00-00-07-0
E11 = E: TURRET; 10th Part Field: 3.3V / 3A; 9th Part Field: FAULT0B; Part Number: MILL-MAX 2501-2-00-80-00-00-07-0
E22 = E: TURRET; 10th Part Field: 3.3V / 3A; 9th Part Field: FAULT1B; Part Number: MILL-MAX 2501-2-00-80-00-00-07-0
E35 = E: TURRET; 10th Part Field: 3.3V / 3A; 9th Part Field: PG0; Part Number: MILL-MAX 2501-2-00-80-00-00-07-0
E36 = E: TURRET; 10th Part Field: 3.3V / 3A; 9th Part Field: PG1; Part Number: MILL-MAX 2501-2-00-80-00-00-07-0
J1 = PEM-kfh-032-10: STUD, TESTPIN; 10th Part Field: 18V - 54V; 9th Part Field: VIN; Part Number: PEM KFH-032-10
J2 = PEM-kfh-032-10: STUD, TESTPIN; 10th Part Field: 5 - 24V #; 9th Part Field: GND; Part Number: PEM KFH-032-10
J3 = PEM-kfh-032-10: STUD, TESTPIN; 10th Part Field: 12V / 12A; 9th Part Field: VOUT0; Part Number: PEM KFH-032-10
J4 J6 = PEM-kfh-032-10: STUD, TESTPIN; 10th Part Field: 12V, MAX 10A; 9th Part Field: GND; Part Number: PEM KFH-032-10
J5 = PEM-kfh-032-10: STUD, TESTPIN; 10th Part Field: 5V / 12A; 9th Part Field: VOUT1; Part Number: PEM KFH-032-10
L1 L3 L4 = IND-RLF7030-OPT_1: IND, 8.6uH; Component: ind; Label: <label>; Manufacturer: VITECH; Manufacturer P/N: 7443630860; Part Number: WURTH ELEKTRONIK 7443630860; Vendor: LTC; Vendor P/N: 59PR9875N; Volts/Amps/Watts: 20A
L2 = IND-RLF7030-OPT_0: IND, 8.6uH; Component: ind; Label: <label>; Manufacturer: VITECH; Manufacturer P/N: 7443630860; Part Number: WURTH ELEKTRONIK 7443630860; Vendor: LTC; Vendor P/N: 59PR9875N; Volts/Amps/Watts: 20A
Q1 Q6 = MOS_FET_6: XSTR, MOSFET N-CH 60V 25A 5 PIN LFPAK; Part Number: RENESAS RJK0651DPB
Q2 Q4 Q5 Q8 = MOS_FET_6: XSTR, OPTION; Part Number: OPTION
Q3 Q7 = MOS_FET_6: XSTR, MOSFET N-CH 60V 45A 5 PIN LFPAK; Part Number: RENESAS RJK0653DPB
Q9 Q10 = MMBT3906LT1_0: XSTR, PNP GENERAL PURPOSE SOT-323; Component: trans; Part Number: DIODES INC. MMST3906-7-F; Part Type: MMBT3906LT1; Vendor P/N: MMBT3906LT1GOSCT-ND
R2 R122 = RES2512_0: RES, 2512 0.006 OHMS 1% 1W; Component: res; Manufacturer: Panasonic; Part Number: PANASONIC ERJ-M1WSF6MU; Tolerance: 1%; Volts/Amps/watts: 1W
R3 R4 = RES0603_9: RES, 0603 1k OHMS 5% 1/10W; Manufacturer: Rohm; Manufacturer P/N: MCR03EZPFX2201; Part Number: VISHAY CRCW06031K00JNEA; Vendor: Digikey; Vendor P/N: RHM2.20KHCT-ND; Volts/Amps/Watts: 0.1W
R5-R7 = RES0603_5: RES, 2512 0 OHM JUMPER OPTION; Label: 1W; Manufacturer: VISHAY; Manufacturer P/N: CRCW251230R0JNEG; Part Number: RN5326 2512 TEPRO NAKOMA OPTION; Tolerance: 5%; Vendor: Digikey; Vendor P/N: 541-30XCT-ND; Volts/Amps/Watts: 0.1W
R8 = RES0603_5: RES, 2512 0 OHM JUMPER OPTION; Label: 1W; Manufacturer: VISHAY; Manufacturer P/N: CRCW251230R0JNEG; Part Number: RN5326 2512 TEPRO NAKOMA OPTION; Tolerance: 5%; Vendor: Digikey; Vendor P/N: 541-30XCT-ND; Volts/Amps/Watts: 1W
R9 = RES0603_9: RES, 0603 2 OHMS 5% 1/10W; Manufacturer: Rohm; Manufacturer P/N: RHM0.0GCT-ND; Part Number: VISHAY CRCW06032R00JNEA; Vendor: Digikey; Vendor P/N: RHM0.0GCT-ND; Volts/Amps/Watts: 0.1W
R10 R11 R13 R15 R16 R18 R23 R25 R28 R112 R113 = RES0603_9: RES, 0603 10k OHMS 5% 1/10W; Manufacturer: Panasonic; Manufacturer P/N: ERJ-3EKF1000V; Part Number: VISHAY CRCW060310K0JNEA; Part Type: CR0402; Vendor: Digikey; Vendor P/N: P100HCT-ND; Volts/Amps/Watts: 0.1W
R12 R30 R38 = RES0603_9: RES, 0603 2 OHMS 5% 1/10W; Manufacturer: Panasonic; Manufacturer P/N: ERJ-3EKF1000V; Part Number: VISHAY CRCW06032R00JNEA; Part Type: CR0402; Vendor: Digikey; Vendor P/N: P100HCT-ND; Volts/Amps/Watts: 0.1W
R14 R58 R70 = RES2512_0: RES, 2010 3m OHMS 1% 1/2W; Component: res; Manufacturer: Panasonic; Manufacturer P/N: ERJ-M1WSF8M0U; Part Number: VISHAY WSL20103L000FEA; Tolerance: 1%; Vendor: Digikey; Vendor P/N: ERJ-M1WTF2M0U; Volts/Amps/watts: 1W
R17 = RES0603_9: RES, 0603 0 OHMS JUMPER; Manufacturer: Rohm; Manufacturer P/N: MCR03EZPFX1000; Part Number: VISHAY CRCW06030000Z0EA; Vendor: Digikey; Vendor P/N: RHM100HCT-ND; Volts/Amps/Watts: 0.1W
R19 R42 = RES0603_9: RES, 0603 OPTION; Manufacturer: Rohm; Manufacturer P/N: MCR03EZPFX2201; Part Number: OPTION; Vendor: Digikey; Vendor P/N: RHM2.20KHCT-ND; Volts/Amps/Watts: 0.1W
R20 R54 R55 R71 R72 = RES0603_9: RES, 0603 OPTION; Manufacturer: Rohm; Manufacturer P/N: RHM0.0GCT-ND; Part Number: OPTION; Tolerance: 5%; Vendor: Digikey; Vendor P/N: RHM0.0GCT-ND; Volts/Amps/Watts: 0.1W
R21 R22 R43 R44 R56 R60 R73 R74 R128-R131 = RES0603_9: RES, 0603 0 OHMS JUMPER; Manufacturer: Rohm; Manufacturer P/N: MCR03EZPFX2201; Part Number: VISHAY CRCW06030000Z0EA; Vendor: Digikey; Vendor P/N: RHM2.20KHCT-ND; Volts/Amps/Watts: 0.1W
R24 R26 = RES0603_9: RES, 0603 100 OHMS 5% 1/10W; Manufacturer: Panasonic; Manufacturer P/N: ERJ-3EKF1000V; Part Number: VISHAY CRCW0603100RJNEA; Vendor: Digikey; Vendor P/N: P100HCT-ND; Volts/Amps/Watts: 0.1W
R27 = RES0603_9: RES, 0603 0 OHMS JUMPER; Manufacturer: Yageo; Manufacturer P/N: RC0603JR-070RL; Part Number: VISHAY CRCW06030000Z0EA; Tolerance: 5%; Vendor: Digikey; Vendor P/N: 311-0.0GRCT-ND; Volts/Amps/Watts: 0.1W
R29 R31-R36 R39-R41 R46 R48 R49 R169 = RES0603_9: RES, 0603 OPTION; Manufacturer: Panasonic; Manufacturer P/N: ERJ-3EKF1000V; Part Number: OPTION; Part Type: CR0402; Vendor: Digikey; Vendor P/N: P100HCT-ND; Volts/Amps/Watts: 0.1W
R37 = RES2512_0: RES, 2010 3m OHMS 1% 1/2W; Component: res; Manufacturer: Panasonic; Manufacturer P/N: ERJ-M1WSF8M0U; Part Number: VISHAY WSL20103L000FEA; Part Type: RES2512; Tolerance: 1%; Vendor: Digikey; Vendor P/N: ERJ-M1WTF2M0U; Volts/Amps/watts: 1W
R45 = RES0603_9: RES, 0603 0 OHMS JUMPER; Manufacturer: Rohm; Manufacturer P/N: RHM0.0GCT-ND; Part Number: VISHAY CRCW06030000Z0EA; Tolerance: 5%; Vendor: Digikey; Vendor P/N: RHM0.0GCT-ND; Volts/Amps/Watts: 0.1W
R47 = RES0603_8: RES, 0603 OPTION; Manufacturer: Rohm; Manufacturer P/N: RHM0.0GCT-ND; Part Number: OPTION; Tolerance: 5%; Vendor: Digikey; Vendor P/N: RHM0.0GCT-ND; Volts/Amps/Watts: 0.1W
R50 R51 = RES0603_9: RES, 0603 100 OHMS 5% 1/10W; Component: res; Manufacturer: Panasonic; Manufacturer P/N: ERJ-3EKF1000V; Part Number: VISHAY CRCW0603100RJNEA; Tolerance: 1%; Vendor: Digikey; Vendor P/N: P100HCT-ND; Volts/Amps/Watts: 0.1W
R90 R92 R94 R95 = RES0603_9: RES, 0805 OPTION; Label: OPT 0; Manufacturer: Rohm; Manufacturer P/N: RHM0.0GCT-ND; Part Number: OPTION; Vendor: Digikey
R118 R121 R148 R173 = RES0603_9: RES, 0603 OPTION; Label: 0; Manufacturer: Rohm; Manufacturer P/N: MCR03EZPFX2201; Part Number: OPTION; Vendor: Digikey; Vendor P/N: RHM2.20KHCT-ND; Volts/Amps/Watts: 0.1W
R124 R125 = RES2512_0: RES, 2512 0 OHMS JUMPER; Component: res; Manufacturer: Panasonic; Manufacturer P/N: ERJ-M1WSF8M0U; Part Number: VISHAY CRCW25120000Z0EG; Tolerance: 1%; Vendor: Digikey; Vendor P/N: ERJ-M1WTF2M0U; Volts/Amps/watts: 1W
R168 = RES0603_9: RES, 0603 0 OHMS JUMPER; Manufacturer: Panasonic; Manufacturer P/N: ERJ-3EKF1000V; Part Number: VISHAY CRCW06030000Z0EA; Part Type: CR0402; Vendor: Digikey; Vendor P/N: P100HCT-ND; Volts/Amps/Watts: 0.1W
U1 = LTC3880-M0001_19: ASSY, IC, WIDE INPUT AND OUTPUT DC/DC CONVERTER; Component: IC; Manufacturer: LTC; Part Number: LINEAS TECH. LTC3886IUKG#10E2-1PBF-ES; Vendor: LTC; Vendor P/N: LTC3880_M0001
C43 = CAP_4: CAP, 0603 4.7uF 10% 16V X5R; Component: cap; Manufacturer: Taiyo Yuden; Manufacturer P/N: LMK212B7475KG-T; Part Number: MURATA GRM188R61C475KAAJD; Tolerance: 10%; Type: cer 0805 X7R; Vendor: Digikey; Vendor P/N: 587-1442-1-ND; Volts/Amps/Watts: 16V
C44 = CAP_3: CAP, 0603 0.1uF 10% 100V X7R; Manufacturer: TDK; Manufacturer P/N: C1608X7R1H104K; Part Number: MURATA GRM188R72A104KA35J; Tolerance: 10%; Type: cer 0603 X7R; Vendor: Digikey; Vendor P/N: 445-1314-1-ND
C45 = CAP_4: CAP, 0603 4.7uF 10% 10V X5R; Component: cap; Manufacturer: Taiyo Yuden; Manufacturer P/N: LMK212B7475KG-T; Part Number: AVX 0603ZD475KAT2A; Tolerance: 10%; Type: cer 0805 X7R; Vendor: Digikey; Vendor P/N: 587-1442-1-ND; Volts/Amps/Watts: 10V
C46-C48 C61 C62 C67 C89 C90 = CAP_3: CAP, 1210 22uF 20% 16V X7R; Component: cap; Manufacturer: TDK; Manufacturer P/N: C3225X5R0J107M; Part Number: MURATA GRM32ER71C226MEA8L; Part Type: CAP1210; Tolerance: 20%; Type: cer 1210 X5R; Vendor: Digikey; Vendor P/N: 445-1437-1-ND; Volts/Amps/Watts: 6.3v
C49 C57 = CAP_3: CAP, 0603 10pF 5% 50V C0G; Manufacturer: TDK; Manufacturer P/N: C1608X7R1H104K; Part Number: AVX 06035A100JAT2A; Tolerance: 10%; Type: cer 0603 X7R; Vendor: Digikey; Vendor P/N: 445-1314-1-ND; Volts/Amps/Watts: 50V
C50 C52 C63 C64 = CAPR12X5_0: CAP, 150uF 16V ELEC. OS-CON; Component: cap; Manufacturer: SANYO; Manufacturer P/N: 6TPF330M9L; Part Number: PANASONIC 16SVP150M; Tolerance: 20%; Type: TANT; Vendor: OS-CON; Volts/Amps/Watts: 6.3V
C54 C60 = CAP_3: CAP, 0603 0.1uF 10% 100V X7R; Component: cap; Manufacturer: TDK; Manufacturer P/N: C1608C0G1H101J; Part Number: MURATA GRM188R72A104KA35J; Tolerance: 5%; Type: cer 0603; Vendor: Digikey; Vendor P/N: 445-1281-1-ND
C55 C68 = CAP_3: CAP, 0603 1nF 10% 16V X7R; Component: cap; Manufacturer: AVX; Manufacturer P/N: 06035C102KAT2A; Part Number: AVX 0603YC102KAT2A; Tolerance: 10%; Type: cer 0603 X7R; Vendor: Digikey; Vendor P/N: 478-1215-1-ND; Volts/Amps/Watts: 50V
C56 = CAP_NP_1_1: CAP, 0603 OPTION; Part Number: OPTION
C69 = CAP_NP_1: CAP, 0603 OPTION; Part Number: OPTION
D4 = DIODE-10MQ100NPbF-SMA-DIODE: DIODE, SCHOTTKY 100V, 1A; Part Number: DIODES/ZETEX, DFLS1100-7
E12 = E: TURRET; 10th Part Field: 3.3V / 3A; 9th Part Field: MODE0; Part Number: MILL-MAX 2501-2-00-80-00-00-07-0
Q11 Q15 = MOSFET_N-DIODE-A-LFPAK_0: XSTR, MOSFET N-CH 60V 25A 5 PIN LFPAK; Part Number: RENESAS RJK0651DPB
Q12 Q14 Q16 Q17 = MOSFET_N-DIODE-A-LFPAK_0: XSTR, OPTION; Part Number: OPTION
Q13 Q18 = MOSFET_N-DIODE-A-LFPAK_0: XSTR, MOSFET N-CH 60V 45A 5 PIN LFPAK; Part Number: RENESAS RJK0653DPB
R52 = RES0603_9: RES, 0603 2 OHMS 5% 1/10W; Manufacturer: Panasonic; Part Number: VISHAY CRCW06032R00JNEA; Vendor: Digikey; Vendor P/N: P100HCT-ND; Volts/Amps/Watts: 0.1W
R53 R67 = RES0603_9: RES, 0603 2 OHMS 5% 1/10W; Component: res; Label: <label>; Manufacturer: Panasonic; Manufacturer P/N: ERJ-3EKF5901V; Part Number: VISHAY CRCW06032R00JNEA; Tolerance: 1%; Vendor: Digikey; Vendor P/N: P5.90KHCT-ND; Volts/Amps/Watts: 0.1W
R57 R59 R61 R62 R64 R66 R69 = RES0603_9: RES, 0603 0 OHMS JUMPER; Component: res; Label: <label>; Manufacturer: Panasonic; Manufacturer P/N: ERJ-3EKF5901V; Part Number: VISHAY CRCW06030000Z0EA; Tolerance: 1%; Vendor: Digikey; Vendor P/N: P5.90KHCT-ND; Volts/Amps/Watts: 0.1W
R63 R65 R75 R76 = RES0603_9: RES, 0603 100 OHMS 5% 1/10W; Manufacturer: Rohm; Manufacturer P/N: RHM0.0GCT-ND; Part Number: VISHAY CRCW0603100RJNEA; Tolerance: 5%; Vendor: Digikey; Vendor P/N: RHM0.0GCT-ND; Volts/Amps/Watts: 0.1W
R68 = RES0603_9: RES, 0603 49.9k OHMS 1% 1/10W; Component: res; Label: <label>; Manufacturer: Panasonic; Manufacturer P/N: ERJ-3EKF5901V; Part Number: VISHAY CRCW060349K9FKEA; Tolerance: 1%; Vendor: Digikey; Vendor P/N: P5.90KHCT-ND; Volts/Amps/Watts: 0.1W
R77 R79 R82 R83 = RES0603_9: RES, 0603 OPTION; Manufacturer: Panasonic; Manufacturer P/N: ERJ-3EKF2002V; Part Number: OPTION; Vendor: Digikey; Vendor P/N: P20.0KHCT-ND; Volts/Amps/Watts: 0.1W
R78 R80 R81 = RES0603_9: RES, 0603 0 OHMS JUMPER; Manufacturer: Panasonic; Manufacturer P/N: ERJ-3EKF2002V; Part Number: VISHAY CRCW06030000Z0EA; Vendor: Digikey; Vendor P/N: P20.0KHCT-ND; Volts/Amps/Watts: 0.1W
U2 = LTC3880-M0001_12: IC, POLYPHASE STEP-DOWN SLAVE CONTROLLER; Component: IC; Manufacturer: LTC; Manufacturer P/N: LTC3880_M0001; Part Number: LINEAR TECH. LTC3870EUFD#PBF; Vendor: LTC; Vendor P/N: LTC3880_M0001
C70 C103 = CAP1206_1: CAP, 0805 2.2uF 10% 16V X7R; Manufacturer: Kemet; Part Number: AVX 0805YC225KAT2A; Tolerance: 10%; Type: cer 1206 X7R; Vendor: Digikey; Vendor P/N: 399-4937-1-ND; Volts/Amps/Watts: 16V
C72 = CAP-NP: CAP, 0603 47nF 10% 25V X7R; Part Number: AVX 06033C473KAT2A
C73 = CAP-NP: CAP, 0603 OPTION; Part Number: OPTION
C74 = CAP-NP: CAP, 1210 2.2uF 10% 100V X7R; 1ST PART FIELD: 100V; Part Number: MURATA GRM32ER72A225KA35L
C75 = UMK325BJ105MH: CAP, 1210 OPTION; 1st Part Field: 10V; Part Number: OPTION
C76 = CAP-NP: CAP, 0603 0.1uF 10% 25V X7R; 1ST PART FIELD: 10V; Part Number: AVX 06033C104KAT2A
C78 = UMK325BJ105MH: CAP, 0805 220nF 10% 100V X7R; 1st Part Field: 100V; Part Number: MURATA GRM21AR72A224KAC5L
C79 C80 = UMK325BJ105MH: CAP, 1210 100uF 20% 10V X5R; 1st Part Field: 10V; Part Number: MURATA GRM32ER61A107ME20L
C81 = CAP-NP: CAP, 0603 220pF 10% 50V X7R; Part Number: AVX 06035C221KAT2A
C100 = CAP_NP: CAP, 0603 150pF 5% 50V NPO; Part Number: AVX 06035A151JAT2A
C84 C101 = CAP_NP: CAP, 0603 100nF 20% 16V X7R; Part Number: AVX 0603YC104MAT2A
C102 = CAP_NP: CAP, 0603 1uF 20% 25V X5R; Part Number: AVX 06033D105MAT2A
D5 D6 D13 D14 = DIODE-LED_2: LED, 0603 GREEN; Label: RED; Manufacturer: PANASONIC; Part Number: OSRAM LG L29K-G2J1-24-Z
D7 = DIODE-LED_2: LED, 0603 RED; Manufacturer: PANASONIC; Part Number: OSRAM LS L29K-H1J2-1-Z
D8 = DIODE_ZENER31_0: DIODE, ZENER OPTION; Part Number: OPTION
E14 = E: TURRET; 10th Part Field: 3.3V / 3A; 9th Part Field: PULSE IN; Part Number: MILL-MAX 2501-2-00-80-00-00-07-0
E16 = E: TURRET; 10th Part Field: 3.3V / 3A; 9th Part Field: IOUT TST; Part Number: MILL-MAX 2501-2-00-80-00-00-07-0
E20 = E: TURRET; 10th Part Field: 3.3V / 3A; 9th Part Field: EXTVCC; Part Number: MILL-MAX 2501-2-00-80-00-00-07-0
E21 = E: TURRET; 9th Part Field: GND; Part Number: MILL-MAX 2501-2-00-80-00-00-07-0
J7 J12 = BNC5-SCH_0: CONN, BNC,5 PINS; Part Number: CONNEX 112404
JP1 = Samtec_TMM-103-02-L-S_0: HEADER, 3 PIN 2mm; 10th Part Field: ITH; 11th Part Field: OFF; 12th Part Field: EXT 5V; 9th Part Field: ON; Part Number: SULLINS NRPN031PAEN-RC
JP5 = Samtec_TMM-103-02-L-S_0: HEADER, 3 PIN 2mm; 10th Part Field: ITH; 11th Part Field: EXT; 12th Part Field: PULSE; 9th Part Field: INT; Part Number: SULLINS NRPN031PAEN-RC
JP6 = Samtec_TMM-103-02-L-S_0: HEADER, 3 PIN 2mm; 10th Part Field: ITH; 11th Part Field: ON; 12th Part Field: PULSE GEN; 9th Part Field: OFF; Part Number: SULLINS NRPN031PAEN-RC
L5 = IND: IND, 68uH; 5th Part Field: SUMIDA CDRH105RNP-680NC; Part Number: SUMIDA CDRH105RNP-680NC
Q19 = MOS_FET_6: XSTR, MOSFET N-CH 30V 30A 5 PIN LFPAK; Part Number: RENESAS RJK0305DPB-00#J0
Q20 = P-MOSFET: XSTR, MOSFET P-CH 20V 5.2A SOT-23; Part Number: VISHAY SI2365EDS-T1-GE3
Q22 Q28 = TRANSISTOR_1: XSTR, MOSFET N-CH 60V 115mA SOT23; Part Number: FAIRCHILD 2N7002A
Q23 Q29 = TRANSISTOR_0: XSTR, MOSFET N-CH 60V 115mA SOT23; Part Number: FAIRCHILD 2N7002A
Q27 = P-MOSFET: XSTR, N-CHANNEL DMOS FET OPTION; Part Number: OPTION
R87 R88 R171 R172 = RES0603_9: RES, 0603 200 OHMS 5% 1/10W; Label: OPT 0; Manufacturer: Rohm; Manufacturer P/N: RHM0.0GCT-ND; Part Number: VISHAY CRCW0603200RJNEA; Tolerance: 5%; Vendor: Digikey; Vendor P/N: RHM0.0GCT-ND; Volts/Amps/Watts: 0.1W
R89 = RES0603_9: RES, 0603 10k OHMS 5% 1/10W; Part Number: VISHAY CRCW060310K0JNEA
R91 = RES0603_5: RES, 2010 0.01 OHMS 1% 1/2W; Label: 1W; Manufacturer: VISHAY; Manufacturer P/N: CRCW251230R0JNEG; Part Number: VISHAY WSL2010R0100FEA; Tolerance: 1%; Vendor: Digikey; Vendor P/N: 541-30XCT-ND; Volts/Amps/Watts: 0.1W
R93 = RES0603_9: RES, 0603 127 OHMS 1% 1/10W; Label: OPT 0; Manufacturer: Rohm; Manufacturer P/N: RHM0.0GCT-ND; Part Number: VISHAY CRCW0603127RFKEA; Tolerance: 5%; Vendor: Digikey; Vendor P/N: RHM0.0GCT-ND; Volts/Amps/Watts: 0.1W
R96 = RES0603_9: RES, 0603 0 OHMS JUMPER; Manufacturer: ROHM; Manufacturer P/N: MCR03EZPFX4991; Part Number: VISHAY CRCW06030000Z0EA
R97 R100 R101 R147 = RES0603_9: RES, 0603 OPTION; Manufacturer: ROHM; Manufacturer P/N: MCR03EZPFX4991; Part Number: OPTION
R98 R174 = RES0603_9: RES, 0603 0 OHMS JUMPER; Manufacturer: ROHM; Manufacturer P/N: MCR03EZPFX4991; Part Number: VISHAY CRCW06030000Z0EA; Volts/Amps/Watts: <Volts/Amps/Watts>
R99 = RES0603_9: RES, 0603 220k OHMS 5% 1/10W; Manufacturer: ROHM; Manufacturer P/N: MCR03EZPFX4991; Part Number: VISHAY CRCW0603220KJNEA
R132 = RES0603_9: RES, 0603 0 OHMS JUMPER; Manufacturer: Rohm; Manufacturer P/N: MCR03EZPFX2201; Part Number: VISHAY CRCW06030000Z0EA
R144 R145 = RES0603_11: RES, 0603 OPTION; Part Number: OPTION
R146 = RES0603_9: RES, 0805 4.7 OHMS 1% 0.125W; Label: OPT 0; Manufacturer: Rohm; Manufacturer P/N: RHM0.0GCT-ND; Part Number: VISHAY CRCW08054R70FKEA; Tolerance: 1%; Vendor: Digikey
R151 = RES0603_0: RES, 0603 1M OHMS 5% 1/10W; Label: OPT 0; Manufacturer: Rohm; Manufacturer P/N: RHM0.0GCT-ND; Part Number: VISHAY CRCW06031M00JNEA; Vendor: Digikey
R152 = RES0603_0: RES, 0603 681K OHMS 1% 1/10W; Manufacturer: ROHM; Manufacturer P/N: MCR03EZPFX4991; Part Number: VISHAY CRCW0603681KFKEA; Tolerance: 1%
R153 = RES0603_0: RES, 0603 3.3 OHMS 1% 1/10W; Manufacturer: ROHM; Manufacturer P/N: MCR03EZPFX4991; Part Number: VISHAY CRCW06033R30FKEA; Tolerance: 1%; Vendor: Digikey
R154 = RES0603_0: RES, 0603 82.5 OHMS 1% 1/10W; Manufacturer: ROHM; Manufacturer P/N: MCR03EZPFX4991; Part Number: VISHAY CRCW060382R5FKEA; Tolerance: 1%; Vendor: Digikey
R155 = RES0603_0: RES, 0603 100 OHMS 5% 1/10W; Manufacturer: ROHM; Manufacturer P/N: MCR03EZPFX4991; Part Number: VISHAY CRCW0603100RJNEA; Vendor: Digikey; Vendor P/N: RHM4.99KHCT-ND; Volts/Amps/Watts: 0.1w
R157 = RES0603_0: RES, 0603 2 OHMS 5% 1/10W; Manufacturer: ROHM; Manufacturer P/N: MCR03EZPFX4991; Part Number: VISHAY CRCW06032R00JNEA; Vendor: Digikey; Vendor P/N: RHM4.99KHCT-ND; Volts/Amps/Watts: 0.1w
R158 = RES0603_0: RES, 0603 27.4k OHMS 1% 1/10W; Manufacturer: Panasonic; Manufacturer P/N: ERJ-3EKF2002V; Part Number: VISHAY CRCW060327K4FKEA; Vendor: Digikey; Vendor P/N: P20.0KHCT-ND; Volts/Amps/Watts: 0.1W
R159 = RES0603_0: RES, 0603 226K OHMS 1% 1/10W; Component: res; Label: <label>; Manufacturer: Panasonic; Manufacturer P/N: ERJ-3EKF5901V; Part Number: VISHAY CRCW0603226KFKEA; Tolerance: 1%; Vendor: Digikey; Vendor P/N: P5.90KHCT-ND; Volts/Amps/Watts: 0.1W
R160 = POT: RES, VARIABLE 5K; Part Number: BOURNS 3386P-1-502-LF
R161 = RES0603_0: RES, 0603 20K OHMS 5% 1/10W; Manufacturer: Panasonic; Manufacturer P/N: ERJ-3EKF2002V; Part Number: VISHAY CRCW060320K0JNEA; Vendor: Digikey; Vendor P/N: P20.0KHCT-ND; Volts/Amps/Watts: 0.1W
R162 = RES2512_0: RES, 1206 0 OHMS JUMPER; Component: res; Manufacturer: Panasonic; Manufacturer P/N: ERJ-M1WSF8M0U; Part Number: VISHAY CRCW12060000Z0EA; Tolerance: 1%; Vendor: Digikey; Vendor P/N: ERJ-M1WTF2M0U; Volts/Amps/watts: 1W
R163 = RES2512_0: RES, 1206 0 OHMS JUMPER OPTION; Component: res; Manufacturer: Panasonic; Manufacturer P/N: ERJ-M1WSF8M0U; Part Number: VISHAY CRCW12060000Z0EA OPTION; Tolerance: 1%; Vendor: Digikey; Vendor P/N: ERJ-M1WTF2M0U; Volts/Amps/watts: 1W
R170 = RES0603_0: RES, 0603 340 OHMS 1% 1/10W; Manufacturer: ROHM; Manufacturer P/N: MCR03EZPFX4991; Part Number: VISHAY CRCW0603340RFKEA; Vendor: Digikey; Vendor P/N: RHM4.99KHCT-ND; Volts/Amps/Watts: 0.1w
U3 = LT3685EMSE_0: IC, SYNCHRONUS STEP-DOWN CONVERTER; Part Number: LINEAR TECH. LTC3630EMSE#PBF
U5 = LT1129CS8-3_1.3: IC, LTC6992; Part Number: LINEAR TECH. LTC6992IS6-1
U6 = LT1129CS8-3_2.3: IC, SINGLE OP AMP; Part Number: LINEAR TECH. LT1803IS5
XJP1-XJP3 XJP5 XJP6 = Samtec_2SN-BK-G_5: SHUNT; Part Number: SAMTEC 2SN-BK-G
C82 C83 = CAP_NP: CAP, 0603 10nF 10% 25V X7R; Part Number: AVX 06033C103KAT2A
D9 D12 = DIODE_SCHOTTKY_9: DIODE, OPTION; Part Number: OPTION
E23-E27 E29 E30 E32 = E_0: TURRET; Part Number: MILL-MAX 2501-2-00-80-00-00-07-0
J9 = PMBUS_HEADER20_3: HEADER, 14PIN DUAL ROW R/A; Component: con; Manufacturer: Mill Max; Manufacturer P/N: 802-40-020-20-0001; Part Number: MOLEX 87760-1416; Part Type: HDR_2X10_RA_REV; Type: header RA 20 dual row; Vendor: LTC; Vendor P/N: 802-40-020-20-001
J10 = PMBUS_CONNECTOR20_3: CONN, SOCKET 14PIN  DUAL ROW R/A; Component: con; Manufacturer: Mill Max; Manufacturer P/N: 803-93-020-20-001; Part Number: SULLINSINC. NPPN072FJFN-RC; Part Type: HDR2X10RA; Type: conn  RA 20 dual row; Vendor: LTC; Vendor P/N: 803-93-020-20-001
J11 = HD2X6-079-PMBUS_2: HEADER, 12PIN 2mm STR DL; Label: DC1427A HEADER; Manufacturer: MOLEX; Manufacturer P/N: 87831-1220; Part Number: FCI 98414-G06-12ULF; Type: header 12POS 2MM VERT; Vendor: Digikey; Vendor P/N: WM18561-ND
JP2 JP3 = Samtec_TMM-103-02-L-S_0: HEADER, 3 PIN 2mm; 10th Part Field: ITH; 11th Part Field: C; 12th Part Field: RUN1; 9th Part Field: NC; Part Number: SULLINS NRPN031PAEN-RC
R102-R105 R108 R110 R111 R117 = RES0603_0: RES, 0603 OPTION; Label: OPT 0; Manufacturer: Rohm; Manufacturer P/N: RHM0.0GCT-ND; Part Number: OPTION; Tolerance: 5%; Vendor: Digikey; Vendor P/N: RHM0.0GCT-ND; Volts/Amps/Watts: 0.1W
R106 = RES0603_0: RES, 0603 0 OHMS JUMPER; Label: OPT 0; Manufacturer: Rohm; Manufacturer P/N: RHM0.0GCT-ND; Part Number: VISHAY CRCW06030000Z0EA; Tolerance: 5%; Vendor: Digikey; Vendor P/N: RHM0.0GCT-ND; Volts/Amps/Watts: 0.1W
R107 = RES0603_3: RES, 1206 OPTION; Label: OPT 0; Manufacturer: Rohm; Manufacturer P/N: RHM0.0GCT-ND; Part Number: OPTION; Tolerance: 5%; Vendor: Digikey; Vendor P/N: RHM0.0GCT-ND; Volts/Amps/Watts: 0.1W
R109 = RES0603_0: RES, 0603 0 OHMS JUMPER; Manufacturer: Rohm; Manufacturer P/N: RHM0.0GCT-ND; Part Number: VISHAY CRCW06030000Z0EA; Tolerance: 5%; Vendor: Digikey; Vendor P/N: RHM0.0GCT-ND; Volts/Amps/Watts: 0.1W
R114 R115 = RES0603_1: RES, 0603 10 OHMS 5% 1/10W; Manufacturer: Rohm; Manufacturer P/N: RHM0.0GCT-ND; Part Number: VISHAY CRCW060310R0JNEA; Tolerance: 5%; Vendor: Digikey; Vendor P/N: RHM0.0GCT-ND; Volts/Amps/Watts: 0.1W
R116 = RES0603_3: RES, 0603 OPTION; Label: OPT 0; Manufacturer: Rohm; Manufacturer P/N: RHM0.0GCT-ND; Part Number: OPTION; Tolerance: 5%; Vendor: Digikey; Vendor P/N: RHM0.0GCT-ND; Volts/Amps/Watts: 0.1W
R119 R120 = RES0603_0: RES, 0603 4.99K OHMS 1% 1/10W; Manufacturer: ROHM; Manufacturer P/N: MCR03EZPFX4991; Part Number: VISHAY CRCW06034K99FKEA; Vendor: Digikey; Vendor P/N: RHM4.99KHCT-ND; Volts/Amps/Watts: 0.1w
SW1 SW2 = JP3X1_079_NO_12_3: SWITCH, SUBMINATURE SLIDE; Part Number: C&K JS202011CQN
U4 = 24LC025-I_SN: IC, 24LC05-I/ST; Part Number: MICROCHIP 24LC025-I/ST
L7 L9 = IND-RLF7030-OPT_1: IND, 6.8uH OPTION; Component: ind; Label: <label>; Manufacturer: VITECH; Manufacturer P/N: 59PR9875N; Part Number: COILCRAFT SER2915H-682KL/SER2918H-682KL OPTION; Vendor: LTC; Vendor P/N: 59PR9875N; Volts/Amps/Watts: 20A
LRE1-LRE10 = Lug_Ring: LUG RING, #10; Part Number: KEYSTONE 8205
MH1-MH4 = CON1: STANDOFF, SNAP ON
NE1-NE20 = NUT: NUT, BRASS 10-32; Part Number: ANY #10-32
WE1-WE10 = Washer: WASHER, #10 TIN PLATED BRASS; Part Number: ANY #10 EXT BZ TN
Y1 Y2 = CON1: DO NOT STUFF; Part Number: PADS ONLY

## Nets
3V3: J11.5(LGKPWR) Q20.2(S) Q27.3(D) R87.1 R88.1 R108.1 R171.1 R172.1
+5V: C101.1 C102.2 JP6.1 JP6.2 R151.1 U5.5(V+) U6.5(V+)
GND_POWER: C1.2 C3.1 C4.1 C5.1 C7.2 C8.2 C10.2 C11.2 C12.2 C14.2 C15.2 C16.2 C17.2 C21.2 C22.2 C24.2 C25.2 C26.2 C29.2 C30.2 C31.2 C32.2 C37.1 C38.1 C39.1 C40.1 C41.2 C42.2 C43.2 C44.2 C45.2 C46.2 C47.2 C48.2 C50.2 C51.2 C52.2 C53.2 C58.2 C59.2 C61.2 C62.2 C63.2 C64.2 C65.2 C66.2 C67.2 C70.2 C71.1 C72.2 C74.2 C75.2 C76.2 C77.1 C79.2 C80.2 C81.2 C82.2 C83.2 C84.2 C85.2 C86.2 C87.2 C88.2 C89.2 C90.2 C91.1 C92.1 C93.2 C94.2 C95.2 C96.2 C97.2 C98.2 C99.2 C101.2 C102.1 C103.2 D8.2(ANODE) E1.1(A) E4.1(A) E8.1(A) E18.1(A) E21.1(A) J2.1 J4.1 J6.1 J7.2 J7.3 J7.4 J7.5 J9.11(GND) J9.12(GND) J10.11(GND) J10.12(GND) J11.3(GND) J11.10(GND) J12.2 J12.3 J12.4 J12.5 JP1.3 Q3.1(S) Q3.2(S) Q3.3(S) Q4.1(S) Q4.2(S) Q4.3(S) Q7.1(S) Q7.2(S) Q7.3(S) Q8.1(S) Q8.2(S) Q8.3(S) Q13.1 Q13.2 Q13.3 Q14.1 Q14.2 Q14.3 Q17.1 Q17.2 Q17.3 Q18.1 Q18.2 Q18.3 Q22.2(S) Q23.2(S) Q28.2(S) Q29.2(S) R27.1 R89.2 R91.1 R93.2 R97.2 R99.1 R132.2 R145.2 R146.2 R147.2 R152.2 R158.1 R160.1(A) R160.2(WIPER) R170.2 SW1.3 SW2.3 U2.19(PGND) U3.8(GND) U3.14(GND) U3.16(GND) U3.17(GND) U4.1(A0) U4.2(A1) U4.3(A2) U4.4(VSS) U4.7(WP) U5.2(GND) U6.2(V-)
GND_SIGNAL: C18.2 C20.2 C27.2 C33.2 C34.2 C36.2 C49.1 C57.1 E32.1(A) Q9.1(BASE) Q9.3(COLLECTOR) Q10.1(BASE) Q10.3(COLLECTOR) R30.1 R32.1 R34.1 R36.1 R40.1 R46.1 R49.1 R68.1 R77.1 R79.1 R82.1 U1.53(GND_SIGNAL) U2.29(GND)
VDD25: C37.2 R31.2 R33.2 R35.2 R39.2 R41.2 R48.2 U1.27(VDD25)
VDD33: C38.2 Q27.2(S) R10.2 R11.2 R13.2 R15.2 R16.2 R18.2 R23.2 R25.2 R28.2 R29.2 R112.1 R113.1 U1.30(VDD33)
VIN: C1.1 C74.1 C78.1 C85.1 C86.1 C87.1 C94.1 C95.1 E3.1(A) J1.1 R2.2 R3.1 R9.1 R100.1 R101.1 R107.1 R122.2 R144.1 U3.3(VIN)
VIN1: C7.1 C8.1 C41.1 C42.1 C58.1 C59.1 C96.1 C98.1 C99.1 Q1.5(D) Q2.5(D) Q11.5 Q12.5 Q15.5 Q16.5 R124.2 R125.2
VIN_PWR: C21.1 C22.1 C97.1 Q5.5(D) Q6.5(D) R2.1 R4.1 R52.1 R122.1 R124.1 R125.1
ALERTB: E23.1(A) J9.3(ALERTB) J10.3(ALERTB) J11.6(ALERTB) Q20.1(G) R15.1 U1.16(~{ALERTB})
AUXVCC: C84.1 J9.8(AUXP) J10.8(AUXP) J11.1(AUXP) R119.1 R120.1 U4.8(VCC)
BG0: Q3.4(G) Q4.4(G) U1.50(BG0)
BG1: Q7.4(G) Q8.4(G) U1.42(BG1)
BOOST0: R12.2 U1.52(BOOST0)
BOOST1: R38.2 U1.40(BOOST1)
EESCL: J11.11(AUXSCL) R119.2 U4.6(SCL)
EESDA: J11.12(AUXSDA) R120.2 U4.5(SDA)
EXT_SUPPLY: C73.1 C75.1 C76.1 C79.1 C80.1 JP6.3 L5.2 R96.1 R174.1
EXTVCC: C43.1 E20.1(A) R174.2 U2.18(EXTVCC)
FAULT0B: D12.2(ANODE) E11.1(A) JP2.1 JP2.2 Q29.1(G) R18.1 R61.1 R64.1 R104.2 R105.2 U1.17(\\~{FAULT}0)
FAULT1B: D9.2(ANODE) E22.1(A) JP2.3 Q28.1(G) R23.1 R102.2 R103.2 U1.18(\\~{FAULT}1)
ILIM: R77.2 R78.1 U2.10(ILIM)
INTVCC: C39.2 D1.2(A) D2.2(A) E2.1(A) U1.44(INTVCC)
INTVCC_2: C45.1 D3.2(A) D4.2 R78.2 R80.2 R83.2 U2.17(INTVCC)
ISENSE0+: C13.1 R24.2 U1.4(ISENSE0+)
ISENSE0-: C13.2 C19.1 R26.2 U1.5(ISENSE0-)
ISENSE1+: C28.1 R50.1 U1.9(ISENSE1+)
ISENSE1-: C28.2 C35.1 R51.1 U1.10(ISENSE1-)
ITH0: C20.1 R57.1 R66.1 R118.1 U1.12(ITH0)
ITH1: C36.1 R118.2 U1.31(ITH1)
ITHR0: C18.1 R173.1 U1.11(ITHR0)
ITHR1: C34.1 R173.2 U1.32(ITHR1)
MODE0: E12.1(A) R81.1 R82.2 R83.1 U2.1(MODE0) U2.8(MODE1)
PG0: E35.1(A) Q23.1(G) R25.1 R81.2 R148.1 U1.34(PGOOD0)
PG1: E36.1(A) Q22.1(G) R28.1 R148.2 U1.33(PGOOD1)
PHASMD: R79.2 R80.1 U2.12(PHASMD)
RUN0: D12.1(CATHODE) E29.1(A) JP3.3 R59.1 R62.1 R103.1 R106.2 R113.2 R115.2 SW1.1 SW1.2 U1.19(RUN0)
RUN1: D9.1(CATHODE) E30.1(A) JP3.1 JP3.2 R105.1 R111.2 R112.2 R114.2 SW2.1 SW2.2 U1.20(RUN1)
SCL: E25.1(A) J9.6(SCL) J10.6(SCL) J11.4(SCL) R11.1 U1.14(SCL)
SDA: E24.1(A) J9.4(SDA) J10.4(SDA) J11.2(SDA) R13.1 U1.15(SDA)
SHARE_CLK: E26.1(A) R16.1 R109.1 U1.29(SHARE_CLK)
SW0: C9.2 L1.1 L7.1 Q1.1(S) Q1.2(S) Q1.3(S) Q2.1(S) Q2.2(S) Q2.3(S) Q3.5(D) Q4.5(D) R19.1 R90.2 U1.1(SW0)
SW0A: L1.2 L7.2 R14.1 R20.1 R21.1
SW1: C23.2 L2.2 L9.2 Q5.1(S) Q5.2(S) Q5.3(S) Q6.1(S) Q6.2(S) Q6.3(S) Q7.5(D) Q8.5(D) R42.1 R92.2 U1.39(SW1)
SW1A: L2.1 L9.1 R37.1 R44.1 R47.2
SW2: C54.2 L3.1 Q11.1 Q11.2 Q11.3 Q12.1 Q12.2 Q12.3 Q13.5 Q14.5 R54.2 R94.2 U2.23(SW0)
SW2A: L3.2 R55.2 R56.1 R58.1
SW3: C60.1 L4.2 Q15.1 Q15.2 Q15.3 Q16.1 Q16.2 Q16.3 Q17.5 Q18.5 R71.2 R95.2 U2.14(SW1)
SW3A: L4.1 R70.1 R72.2 R73.1
SYNC: E27.1(A) R10.1 R69.1 R110.1 U1.13(SYNC)
TG0: R128.1 U1.2(TG0)
TG1: R129.1 U1.38(TG1)
TSNS0: C27.1 Q9.2(EMITTER) U1.6(TSNS0)
TSNS1: C33.1 Q10.2(EMITTER) U1.36(TSNS1)
VOUT0: C10.1 C11.1 C12.1 C14.1 C15.1 C16.1 C17.1 C46.1 C47.1 C48.1 C50.1 C51.1 C52.1 C53.1 C61.1 C62.1 C63.1 C64.1 C65.1 C66.1 C67.1 C70.1 C88.1 C89.1 C90.1 J3.1 J7.1 R5.2 R6.2 R7.2 R8.2 R14.2 R17.1 R22.1 R58.2 R60.1 R70.2 R74.1 R162.1 R168.1
VOUT1: C24.1 C25.1 C26.1 C29.1 C30.1 C31.1 C32.1 C93.1 C103.1 J5.1 J12.1 R5.1 R6.1 R7.1 R8.1 R37.2 R43.1 R45.1 R163.1 R169.1
VSENSE0+: E5.1(A) R17.2 R121.1 U1.7(VSENSE0+)
VSENSE0-: E6.1(A) R27.2 U1.8(VSENSE0-)
VSENSE1: E7.1(A) R45.2 R121.2 U1.35(VSENSE1+)
WP: R29.1 R30.2 U1.28(WP)
N18162459: C57.2 R66.2 U2.9(ITH1)
N18162594: C60.2 D4.1 R67.2
N18162598: Q17.4 Q18.4 U2.16(BG1)
N18162719: R53.1 U2.22(BOOST0)
N18162723: R59.2 U2.4(RUN0)
N18162735: C54.1 D3.1(K) R53.2
N18162778: C44.1 R52.2 U2.20(VIN)
N18162821: R130.1 U2.24(TG0)
N18162858: C49.2 R57.2 U2.28(ITH0)
N18162931: Q13.4 Q14.4 U2.21(BG0)
N18162940: R68.2 U2.27(FREQ)
N18163033: Q15.4 Q16.4 R131.2
N18163121: Q11.4 Q12.4 R130.2
N18163294: R71.1 R73.2 R75.1
N18163455: R62.2 U2.5(RUN1)
N18206199: C56.1 R55.1 R60.2 R65.1
N18210393: R131.1 U2.13(TG1)
N18214499: C55.2 R63.2 U2.2(ISENSE0+)
N18215497: C55.1 C56.2 R65.2 U2.3(ISENSE0-)
N18231098: R54.1 R56.2 R63.1
N18241787: R67.1 U2.15(BOOST1)
N18249474: C68.1 C69.2 R76.2 U2.6(ISENSE1-)
N18249484: C69.1 R72.1 R74.2 R76.1
N18253058: C68.2 R75.2 U2.7(ISENSE1+)
N19848393: C91.2 R94.1
N20549080: J11.8(OUTEN_0) R116.1
N20549082: J11.9(OUTEN_1) R117.1
N20549096: J9.2(CTRL) J10.2(CTRL) R106.1 R111.1 R116.2 R117.2
N20549100: J9.13(12V) J9.14(12V) J10.13(12V) J10.14(12V) R107.2
N20549243: C82.1 R114.1
N20549256: J9.10(UNUSED) J10.10(UNUSED) R108.2
N20549273: C83.1 R115.1
N20549287: J9.5(SHARE_CLK) J10.5(SHARE_CLK) R109.2
N20549363: J9.9(UNUSED) J10.9(UNUSED) R110.2
N20549437: J9.1(FAULTB) J10.1(FAULTB) R102.1 R104.1
N20549487: J9.7(RESETB) J10.7(RESETB)
N20554796: R41.1 R46.2 U1.25(FREQ_CFG)
N20554918: R48.1 R49.2 U1.26(PHAS_CFG)
N20554976: C35.2 R43.2 R47.1 R51.2
N20555079: C9.1 D1.1(K) R12.1
N20555212: C77.2 R92.1
N20555214: Q1.4(G) Q2.4(G) R128.2
N20555355: Q5.4(G) Q6.4(G) R129.2
N20555436: C5.2 C6.1 R4.2 U1.46(IIINM)
N20555456: R42.2 R44.2 R50.2
N20555530: C23.1 D2.1(K) R38.1
N20555598: C40.2 R168.2 R169.2 U1.43(EXTVCC)
N20555669: C4.2 C6.2 R3.2 U1.47(IINP)
N20555715: C71.2 R90.1
N20555757: C3.2 R9.2 U1.48(VIN)
N20555854: R31.1 R32.2 U1.21(ASEL0)
N20556038: C19.2 R20.2 R22.2 R26.1
N20556154: R33.1 R34.2 U1.22(ASEL1)
N20556179: R35.1 R36.2 U1.23(VOUT0_CFG)
N20556187: R39.1 R40.2 U1.24(VOUT1_CFG)
N20556217: R19.2 R21.2 R24.1
N20562366: JP5.1 R153.2
N20562368: JP5.2 JP5.3 Q19.4(G) R89.1 R157.2
N20562376: E16.1(A) Q19.1(S) Q19.2(S) Q19.3(S) R91.2 R154.2
N20562382: E14.1(A) R157.1
N20562418: Q19.5(D) R162.2 R163.2
N20562513: C73.2 R96.2 R97.1 U3.9(VFB)
N20562533: R98.1 U3.7(VPRG1)
N20562535: R132.1 U3.6(VPRG2)
N20562540: C72.1 R98.2 U3.10(SS)
N20562801: L5.1 U3.1(SW)
N20562899: JP1.2 U3.5(RUN)
N20562907: C78.2 R146.1
N20563002: D8.1(CATHODE) JP1.1 R100.2 R147.1
N20563074: C81.1 R99.2 R101.2 U3.11(ISET)
N20563129: C100.2 R153.1 U6.1(VOUT)
N20563131: R155.1 R161.1 U6.3(+IN)
N20563149: R151.2 R152.1 U5.4(DIV)
N20563171: R161.2 U5.6(OUT)
N20563173: R155.2 R160.3(B) R170.1
N20563252: R158.2 R159.1 U5.1(MOD)
N20563280: C100.1 R154.1 U6.4(-IN)
N20563334: R159.2 U5.3(SET)
N20563414: Q27.1(G) R144.2 R145.1
N20563495: D6.2(A) R87.2
N20563497: D6.1(K) Q23.3(D)
N20563528: D5.1(K) Q22.3(D)
N20563532: D7.2(A) Q20.3(D)
N20563579: D5.2(A) R88.2
N20563596: D7.1(K) R93.1
N20563622: D14.2(A) R172.2
N20563624: D14.1(K) Q29.3(D)
N20563646: D13.1(K) Q28.3(D)
N20563683: D13.2(A) R171.2
N20599538: C92.2 R95.1
N20599539: R69.2 U2.11(SYNC)
N20599540: R64.2 U2.25(~{FAULT1})
N20599541: R61.2 U2.26(~{FAULT0})

Not connected (* = marked no-connect by the designer): J11 7(GPIO_1); MH1 1; MH2 1; MH3 1; MH4 1; SW1 4 5 6; SW2 4 5 6; U1 3(NC) 37(NC) 41(NC) 45(NC) 49(NC) 51(NC); U3 12(FBO); Y1 1; Y2 1

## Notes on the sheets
sheet 1
- ALL PARTS ON THIS PAGE ARE, NOT STUFFED IN THE -A VERSION
- 0
- 16V
- 16V
- 16V
- 16V
- 1210
- 0
- 16V
- 16V
- 1210
- 0
- 0
- 16V
- 16V
- Thursday, June 02, 2016
- AND DIGITAL POWER MANAGEMENT
sheet 2
- 2
- 2
- 2
- 2
- 3m
- 1210
- 16V
- OPT
- OPT
- 0
- 0
- 100
- 1nF
- 100
- OS-CON
- OS-CON
- 7343
- OPT
- 7343
- OPT
- 16V
- 16V
- OPT
- 3m
- 1210
- 16V
- 16V
- OPT
- OPT
- 0
- 0
- 100
- 1nF
- 100
- 7343
- OS-CON
- OS-CON
- 7343
- OPT
- OPT
- 16V
- 16V
- OPT
- 2
- NOTE: UNLESS OTHERWISE SPECIFIED
- 2
- 2
- 2
- 1.  ALL RESISTORS AND CAPACITORS ARE 0603.
- 2   FOR -A OPTION.
- Thursday, June 02, 2016
- NOTE:
  T1 - T8 ARE EXPOSED PCB VIAS
  FOR USE AS TEST POINTS
- NOTE:
  VOUT0 AND VOUT1 DEFAULT OUTPUT = 1.8V
- LTC3880EUJ - CURRENT MODE DUAL PHASE / DUAL CHANNEL
  STEP-DOWN CONTROLLER WITH I2C / PMBus INTERFACE
- MAKE ALL SENSE CONNECTIONS TO L1/L2
  AND R10/R16 DIFFERENTIAL AND KELVIN
sheet 3
- ALL PARTS ON THIS PAGE ARE FOR DEMO ONLY, NOT NEEDED IN CUSTOMER DESIGN
- DYNAMIC LOAD CIRCUIT
- DO NOT EXCEED 5% DUTY CYCLE!
- 48Hz,
- Less Than 3% Duty Cycle
- NOTE:
  PULSE OUT
  10mV / AMP
- VOUT0
- VOUT1
- PG0
- PG1
- ALERTB
- FAULT0B
- FAULT1B
sheet 4
- ALL PARTS ON THIS PAGE ARE FOR DEMO ONLY, NOT NEEDED IN CUSTOMER DESIGN
- FAULT0B-FAULT1B
- RUN0-RUN1
- TO DC1613A
- RUN1
- RUN0
- ON
- ON
- OFF
- OFF
- Thursday, June 02, 2016
sheet 5
- USED TO ASSEMBLE PCB
- USED TO MANUFACTURE PCB
- REPRESENTS STAND OFFS
- REPRESENTS TOOLING HOLES
